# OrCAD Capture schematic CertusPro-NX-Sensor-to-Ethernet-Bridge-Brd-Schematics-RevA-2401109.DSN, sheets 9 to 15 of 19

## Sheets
9 CrossLink_Bank 0,1,3: size B
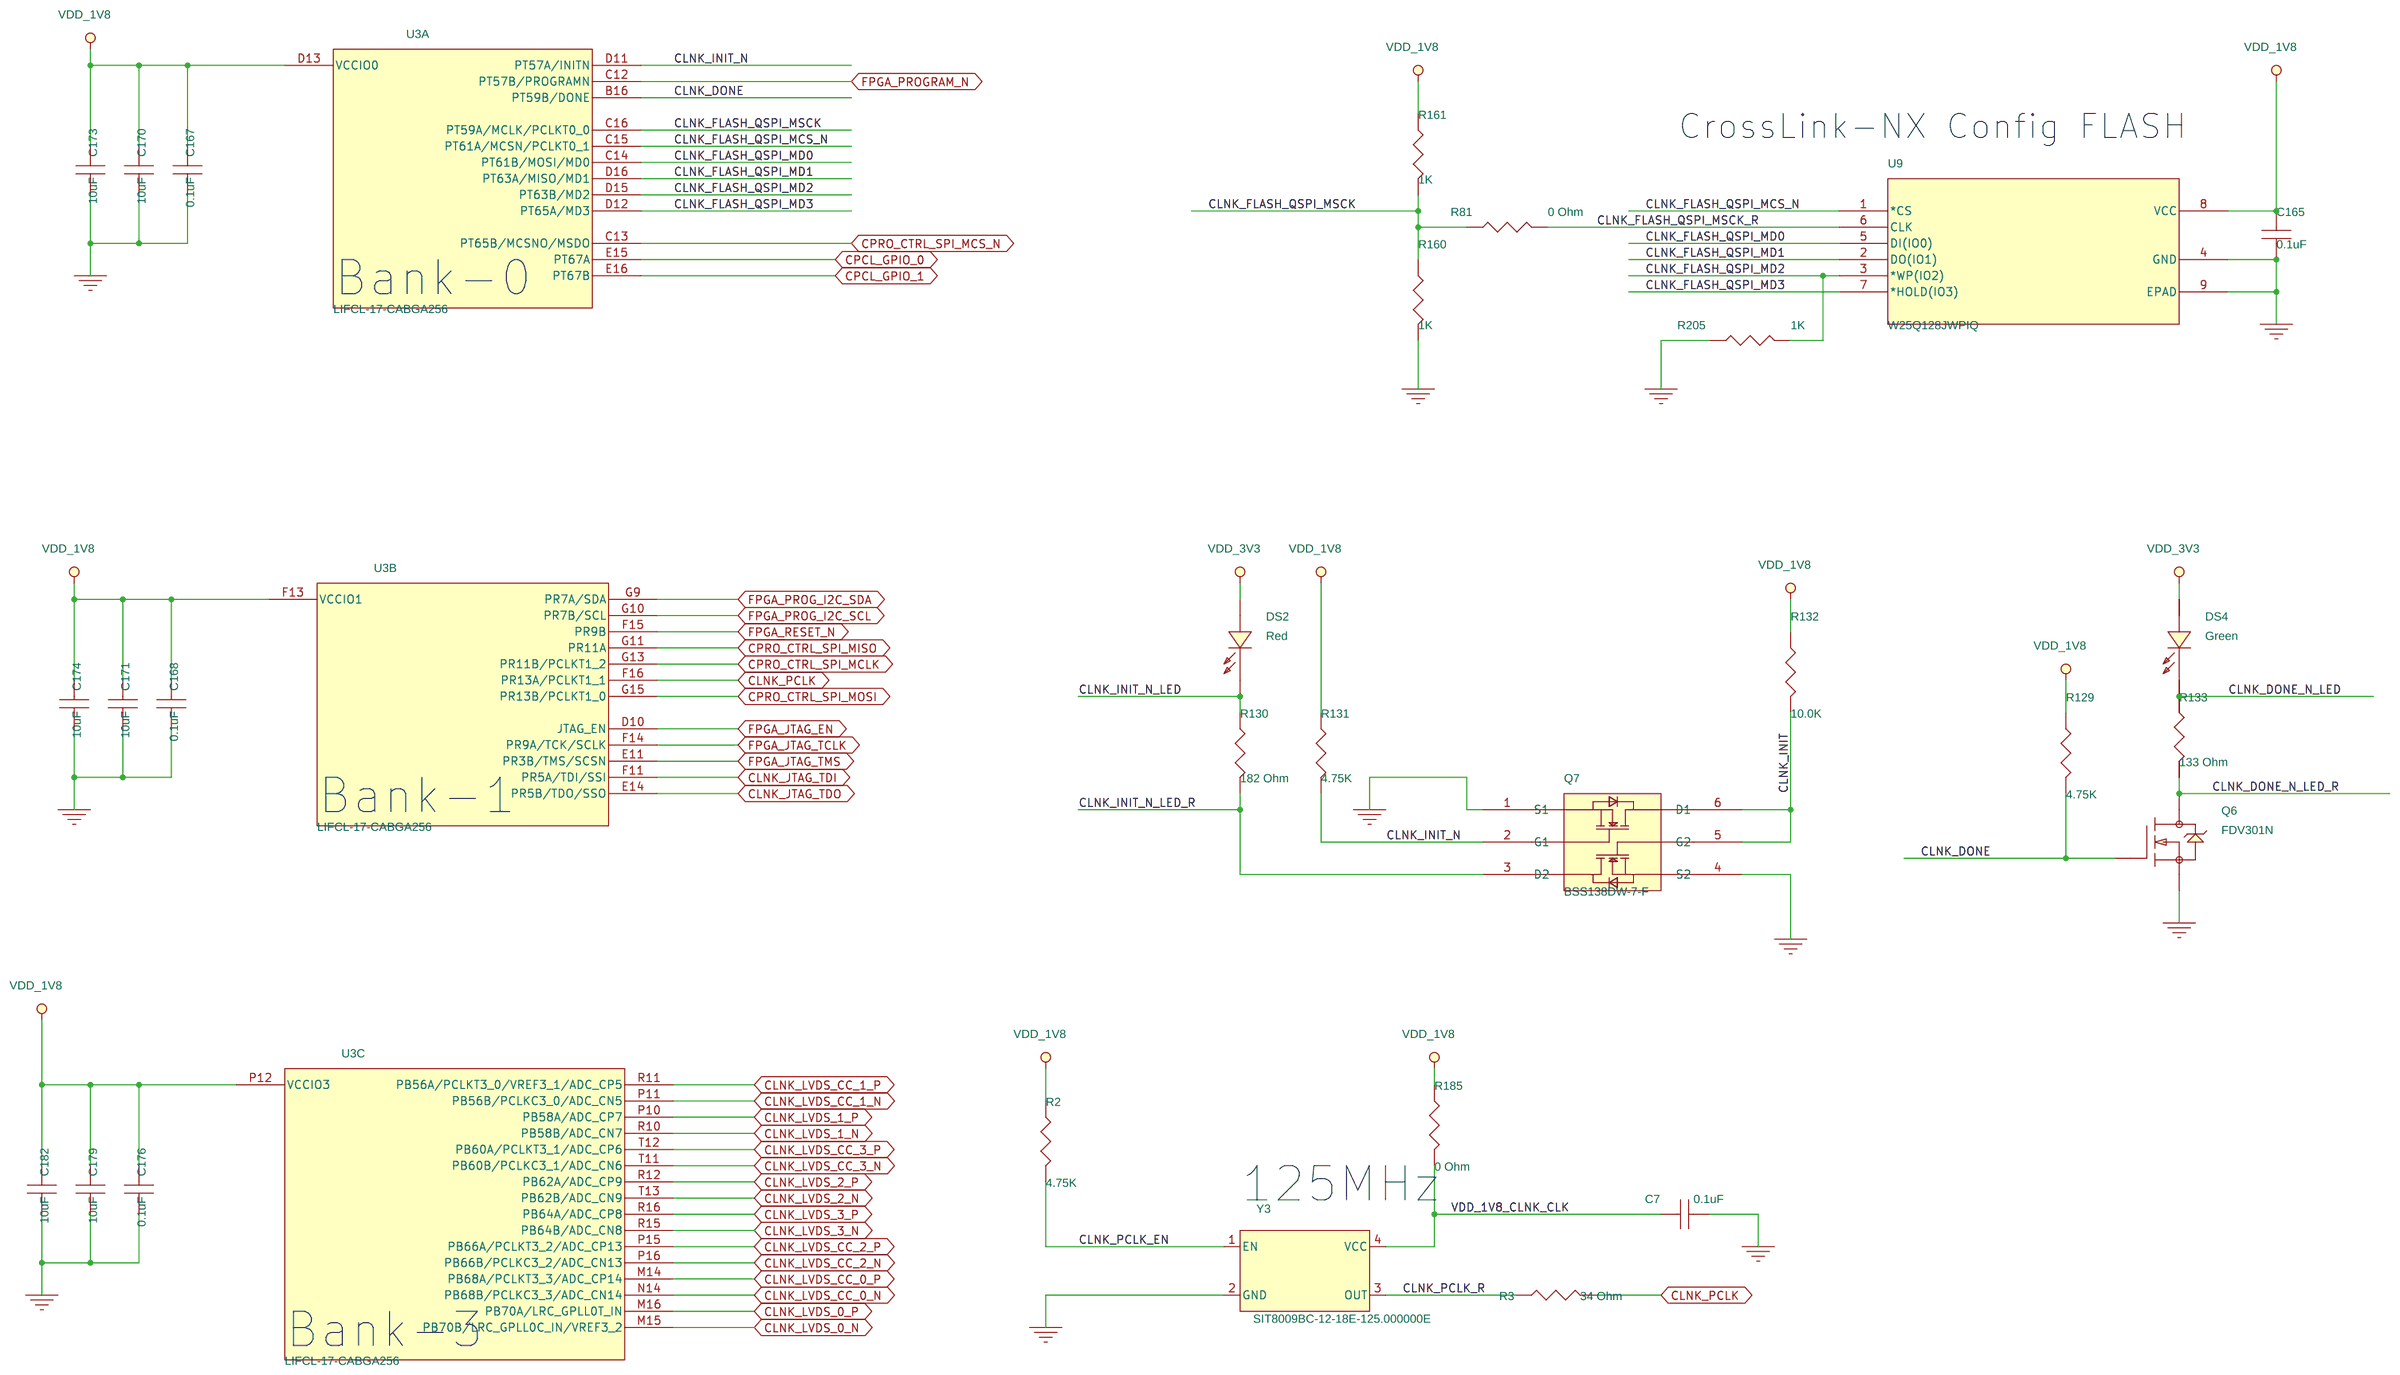
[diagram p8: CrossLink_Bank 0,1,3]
10 CrossLink_Bank 4,5,6,7: size B
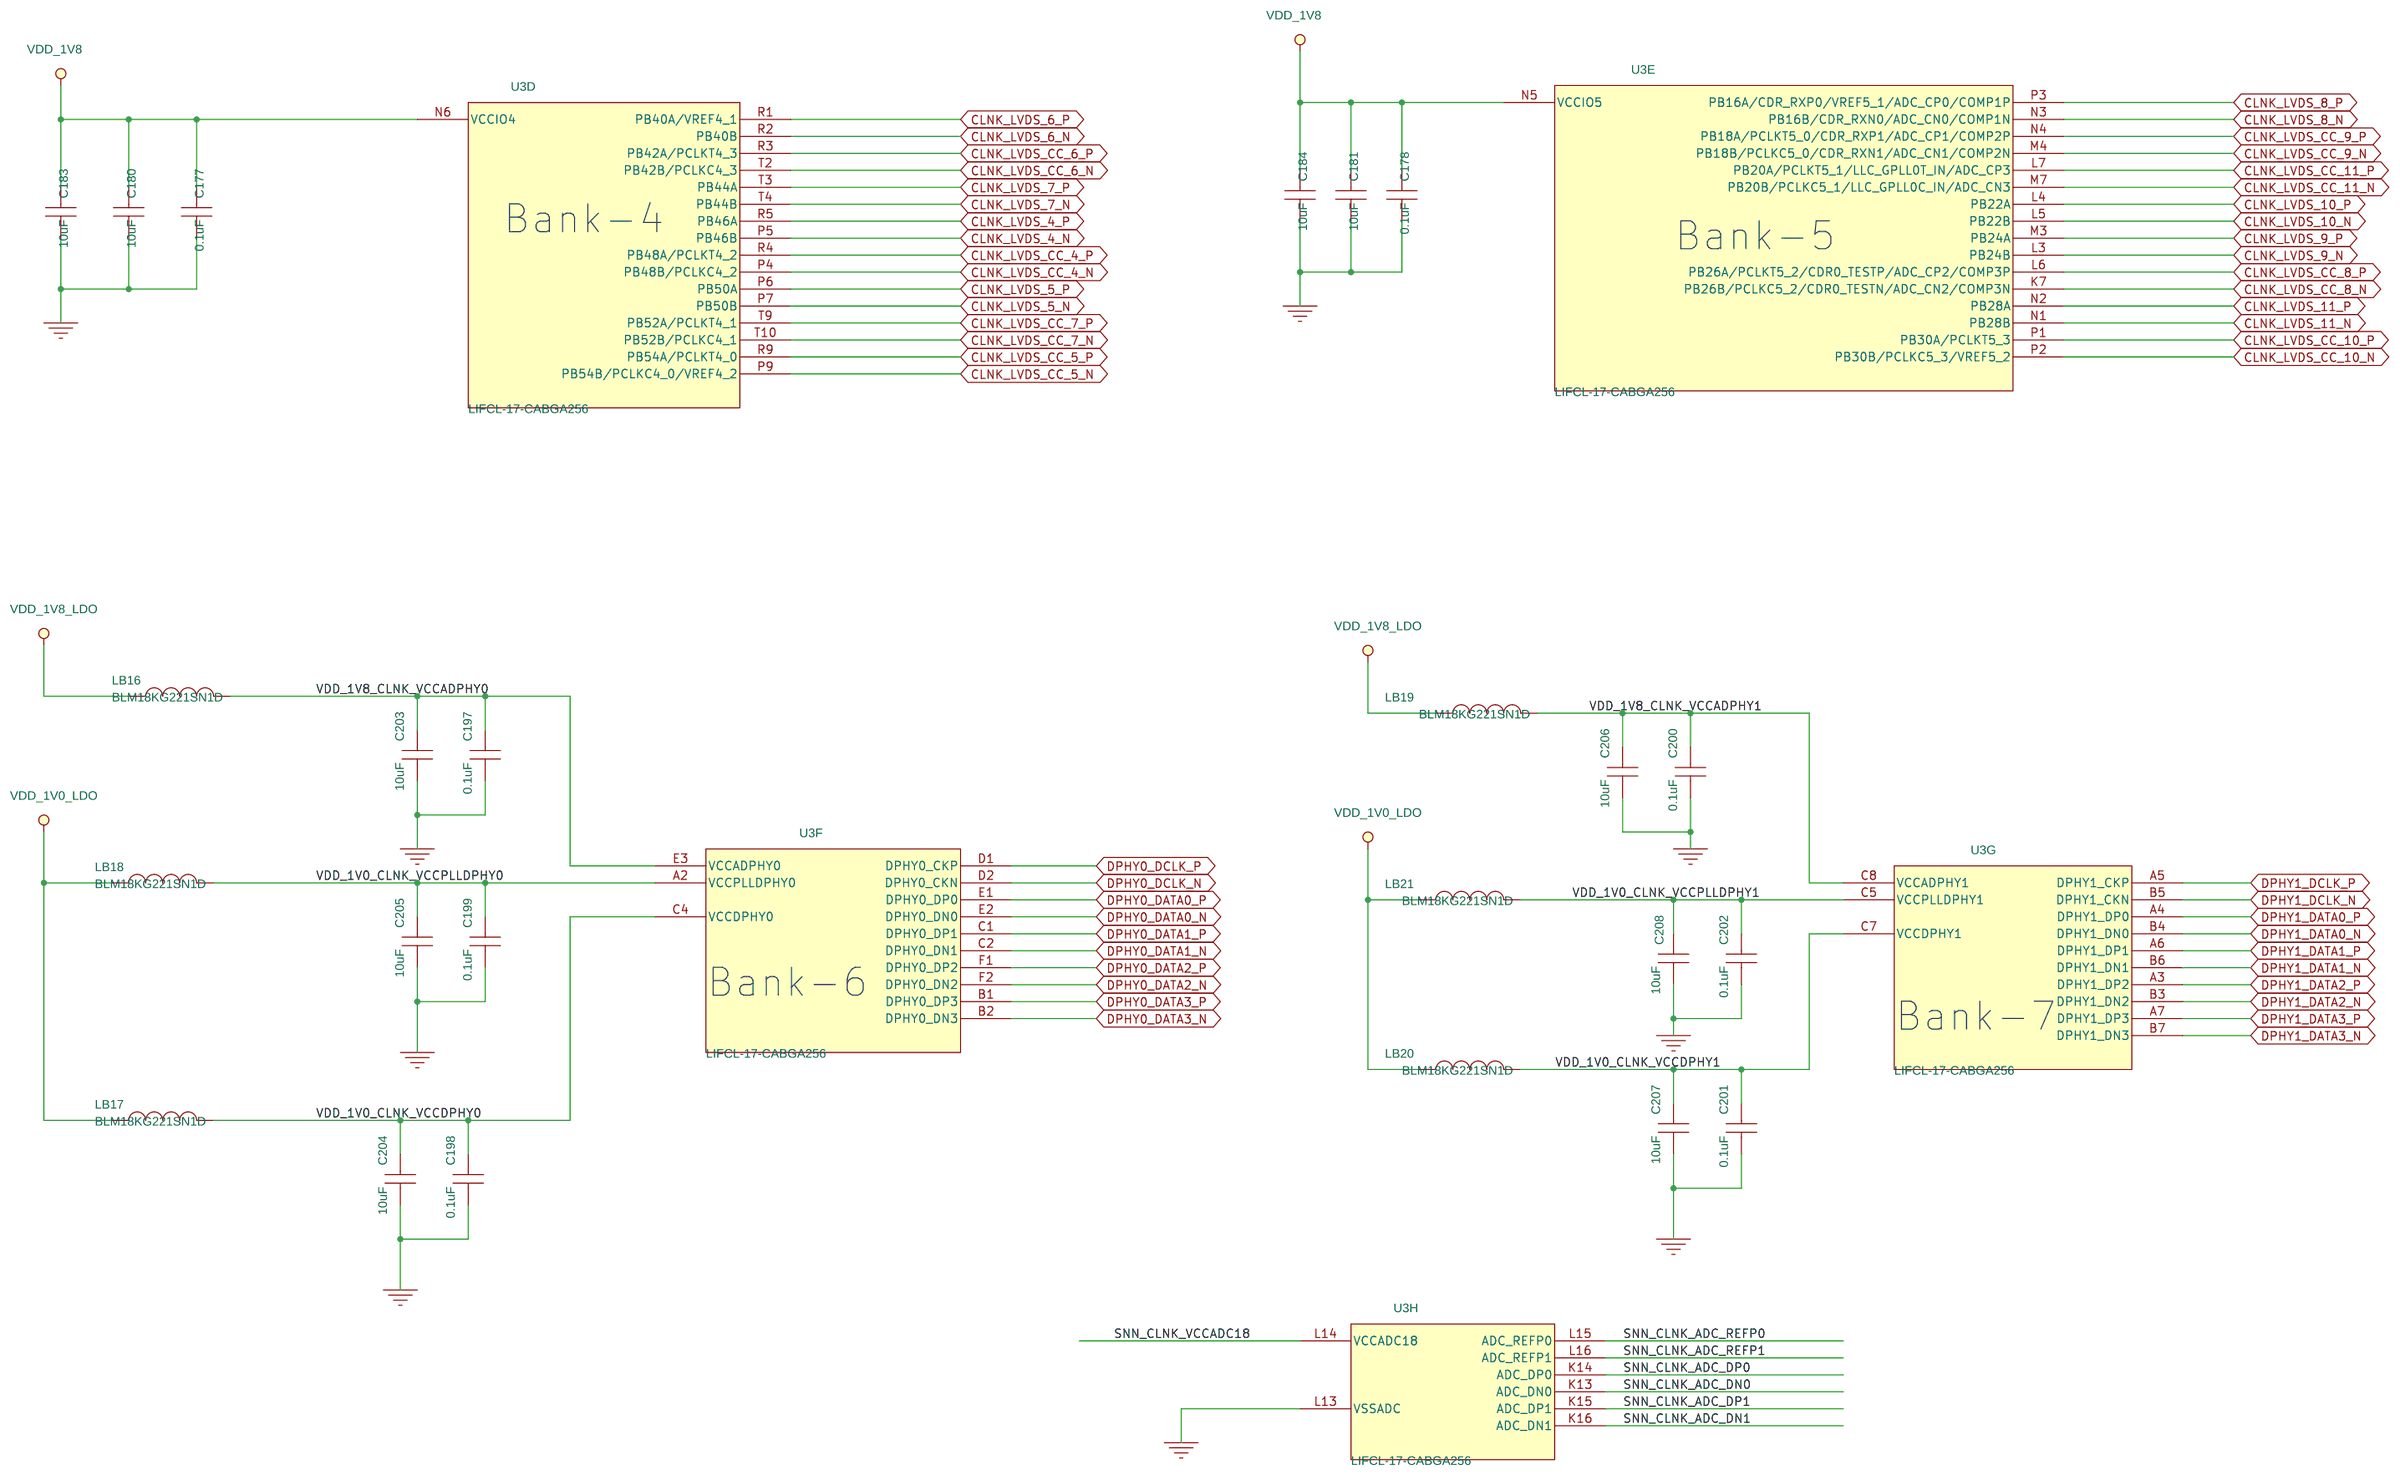
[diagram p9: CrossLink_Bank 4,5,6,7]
11 CrossLink_Power, GND: size B
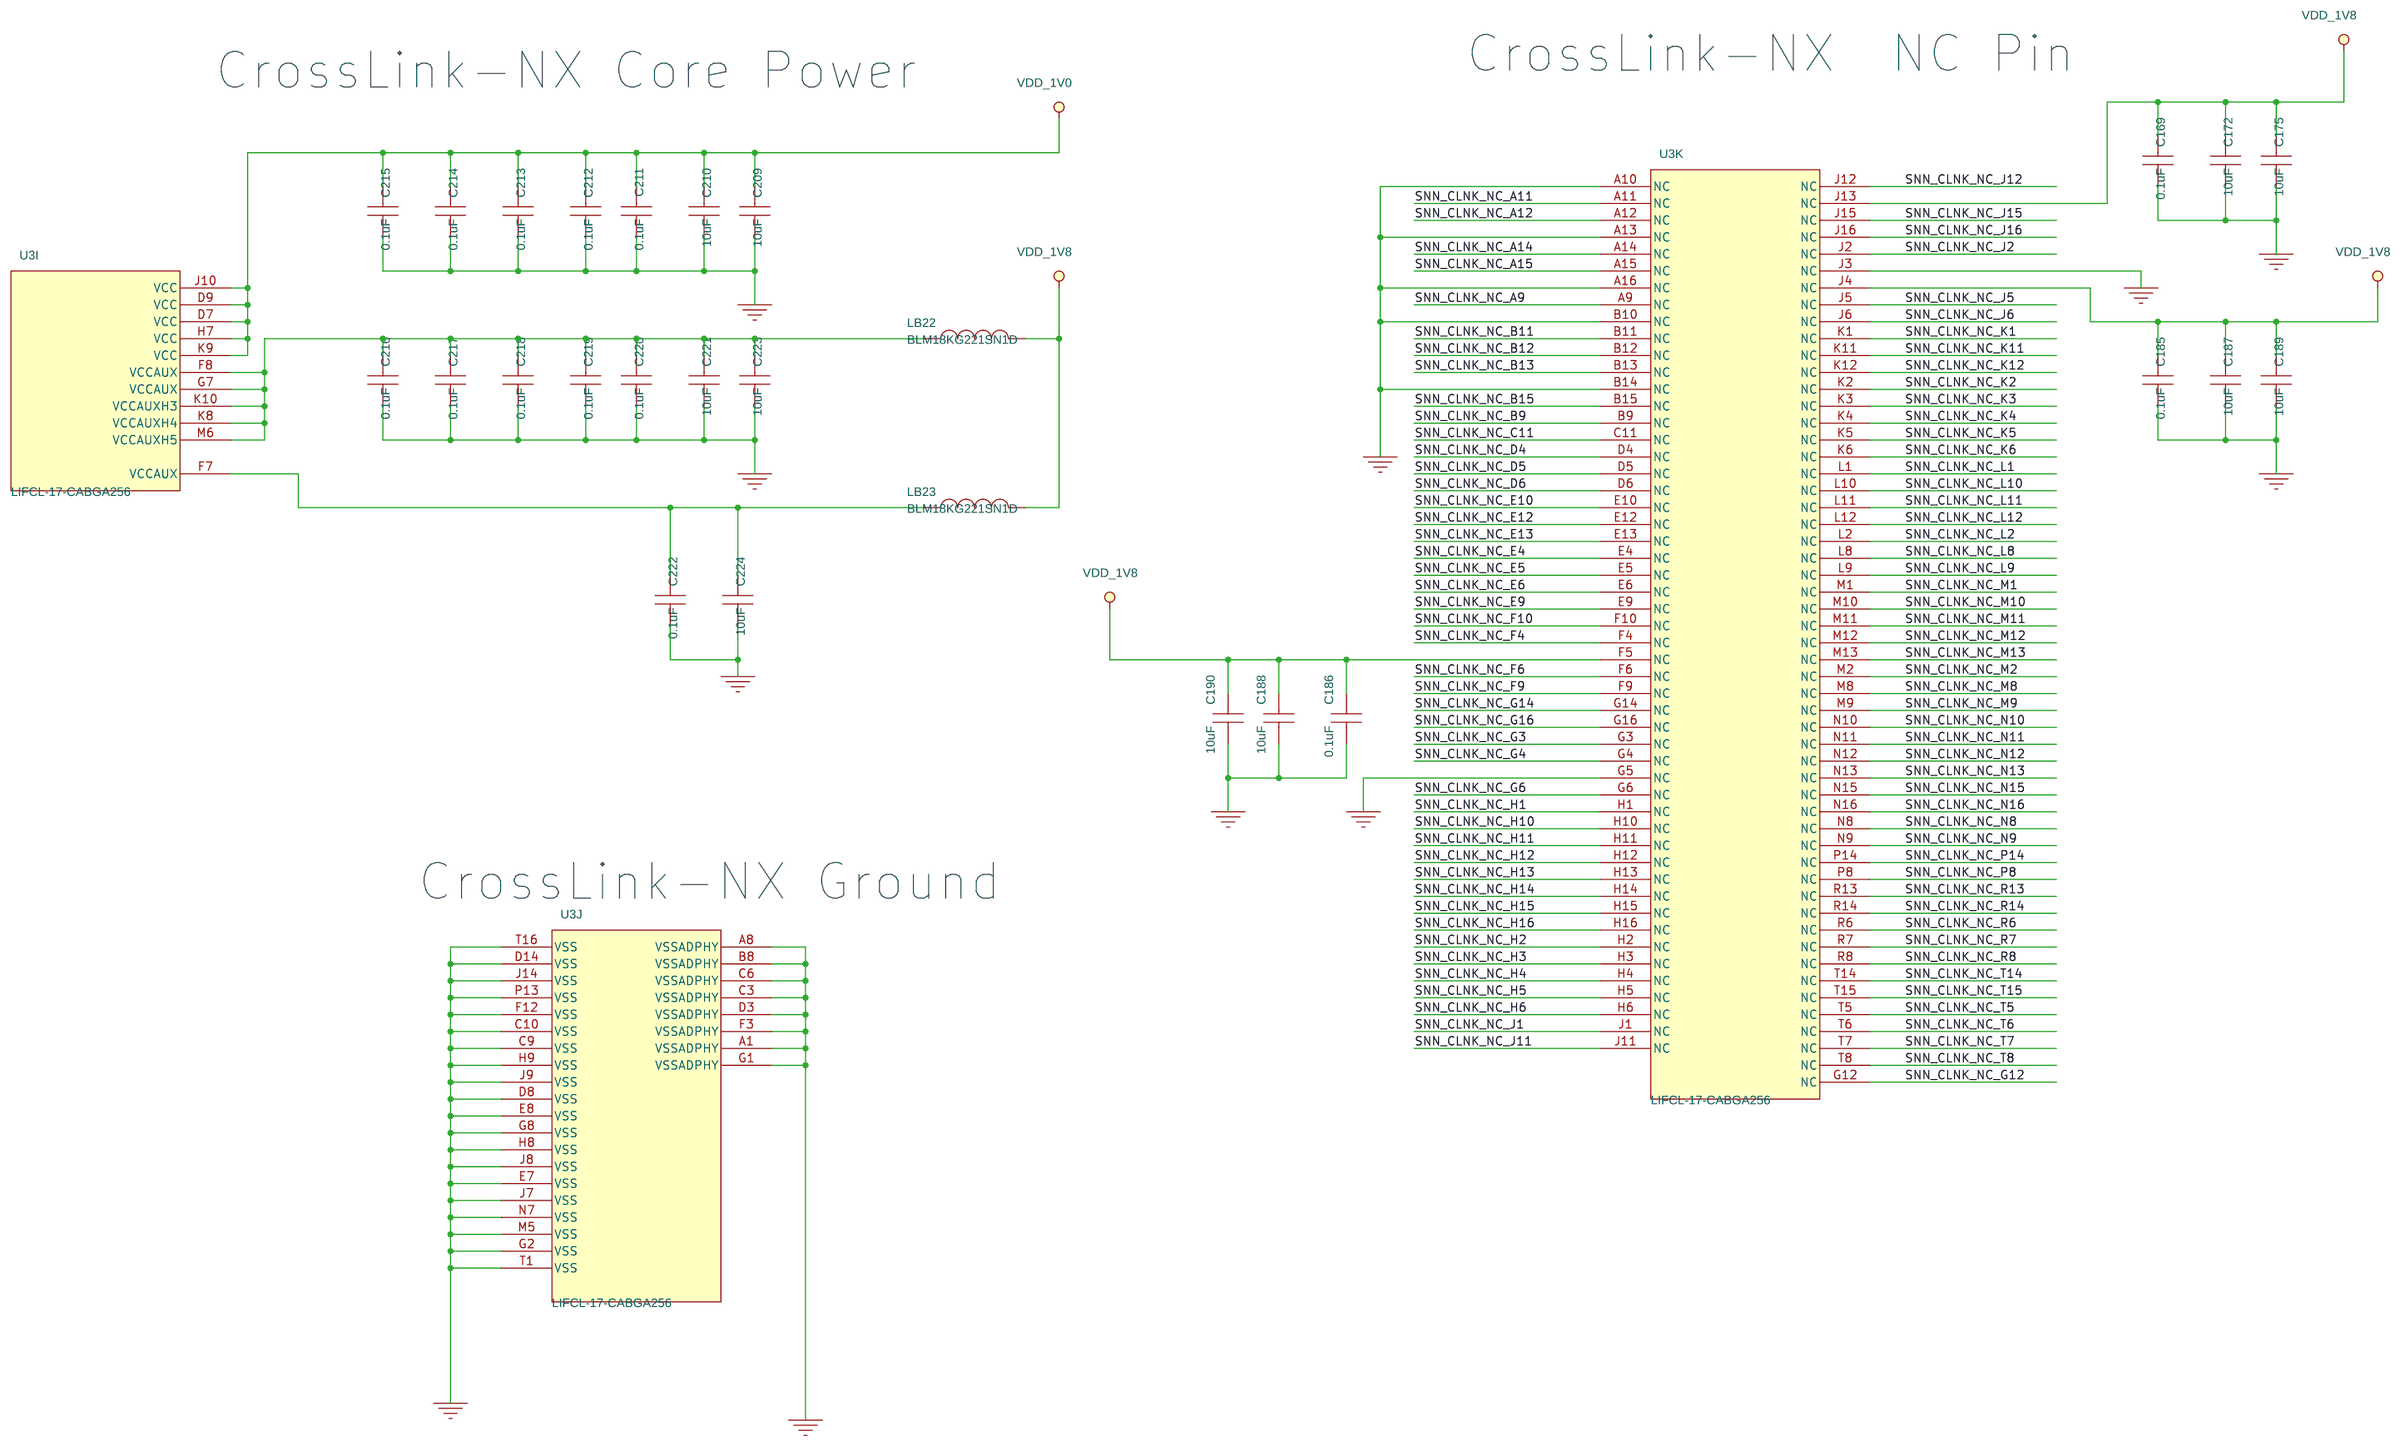
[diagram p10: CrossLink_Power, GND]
12 Camera Connector Interface: size B
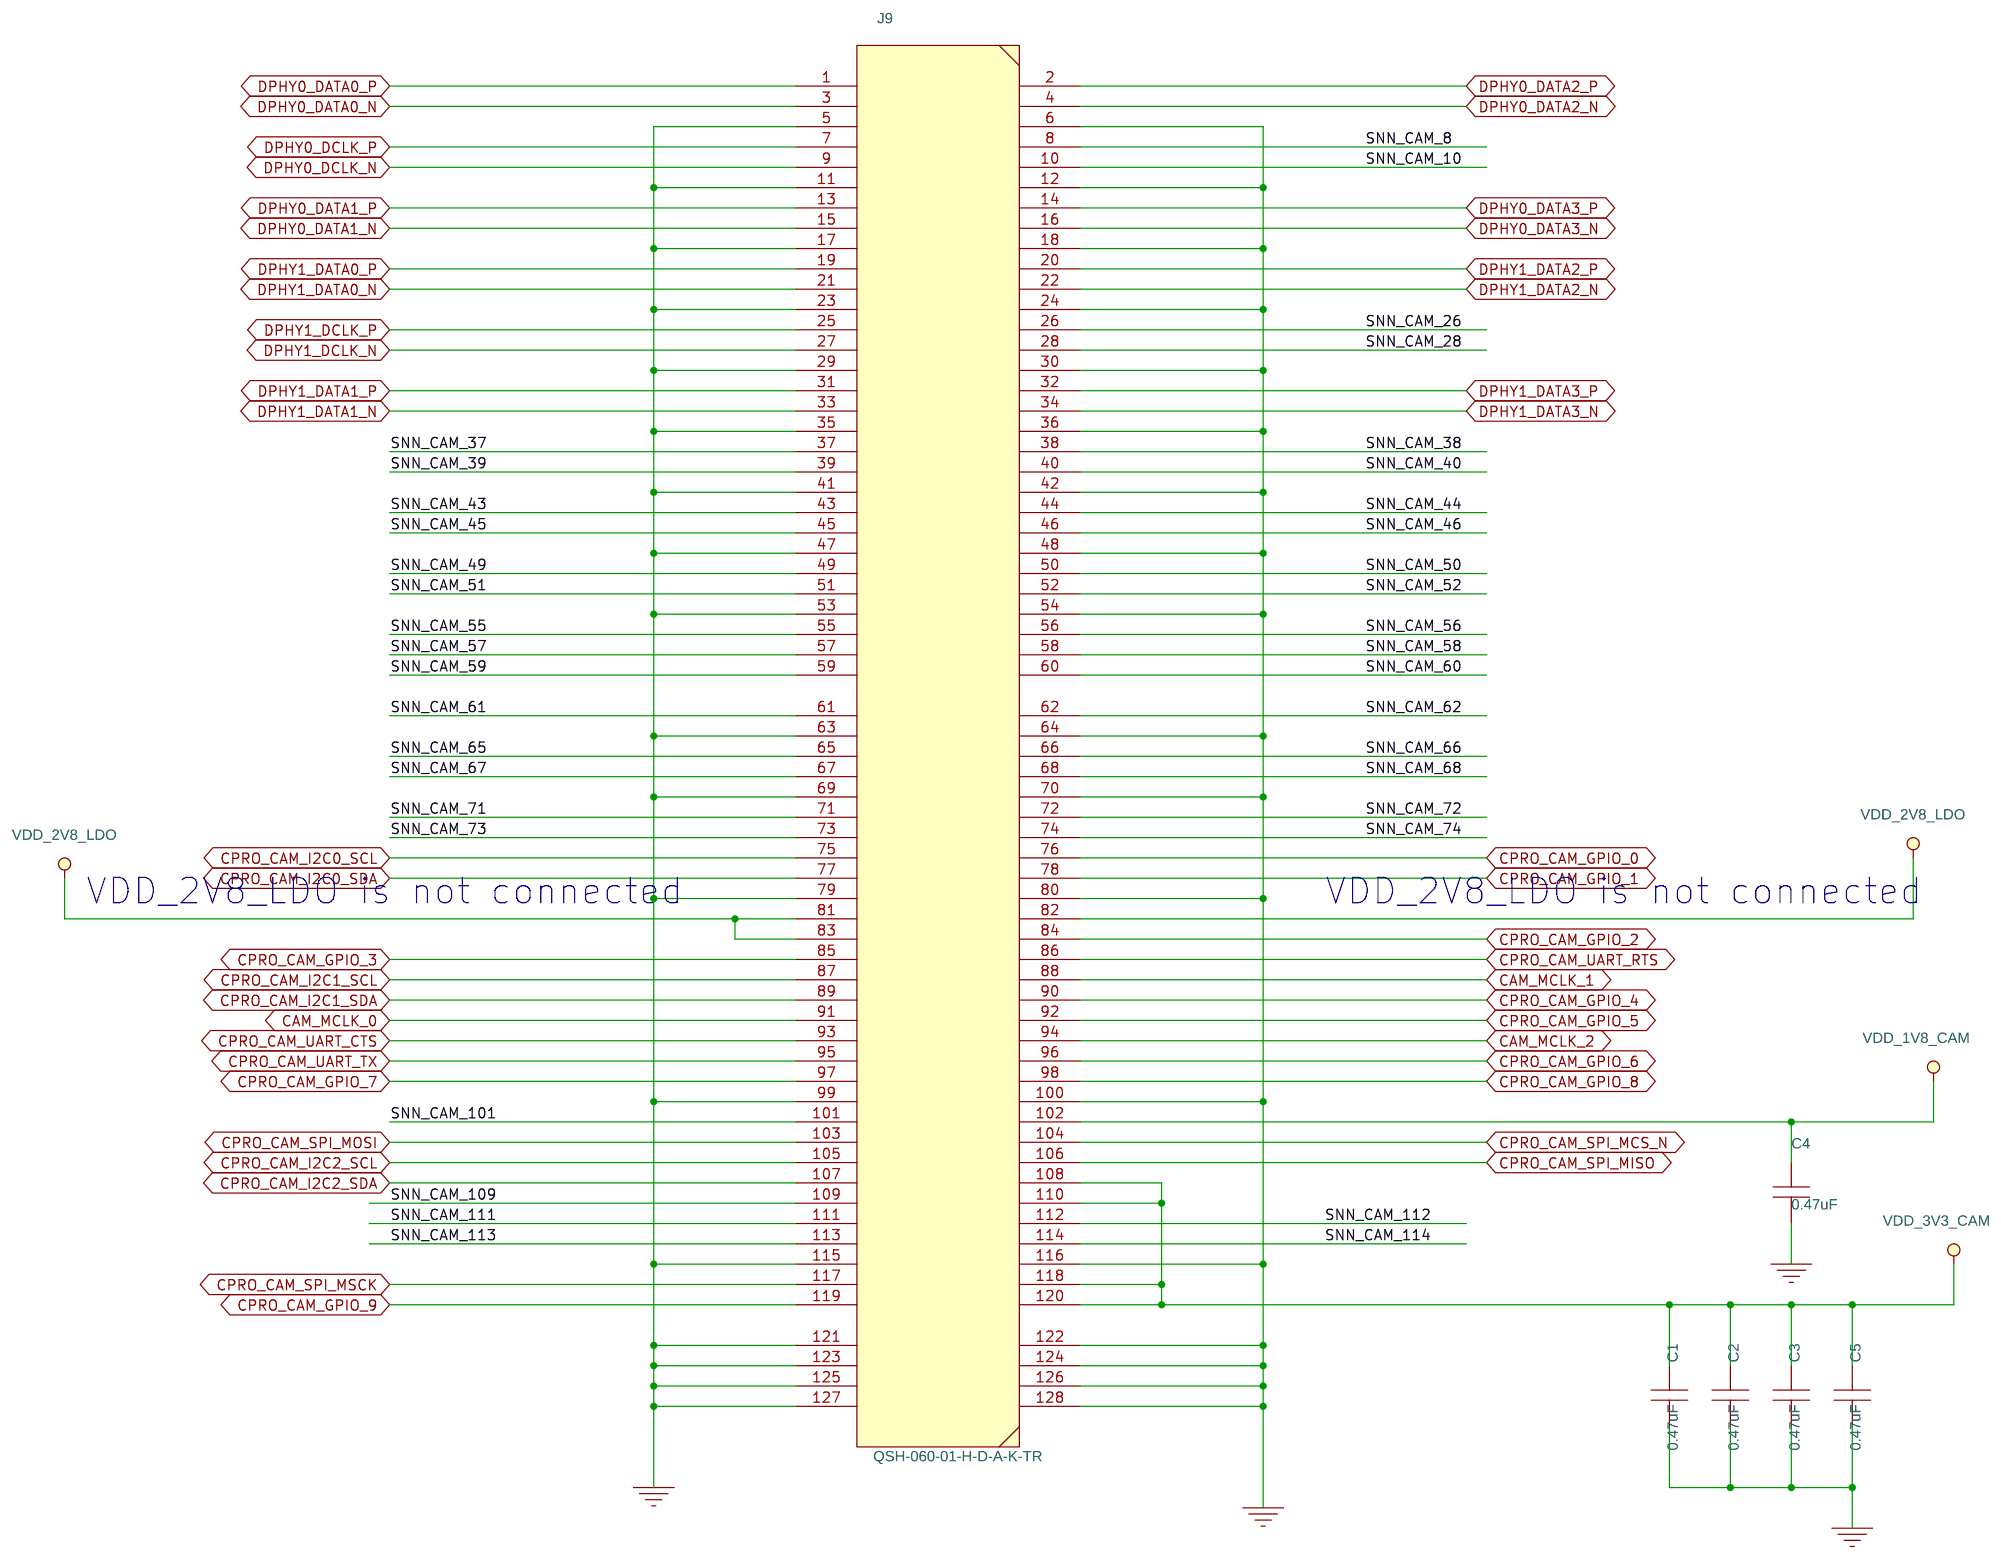
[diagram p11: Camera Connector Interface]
13 FMC HPC: size B
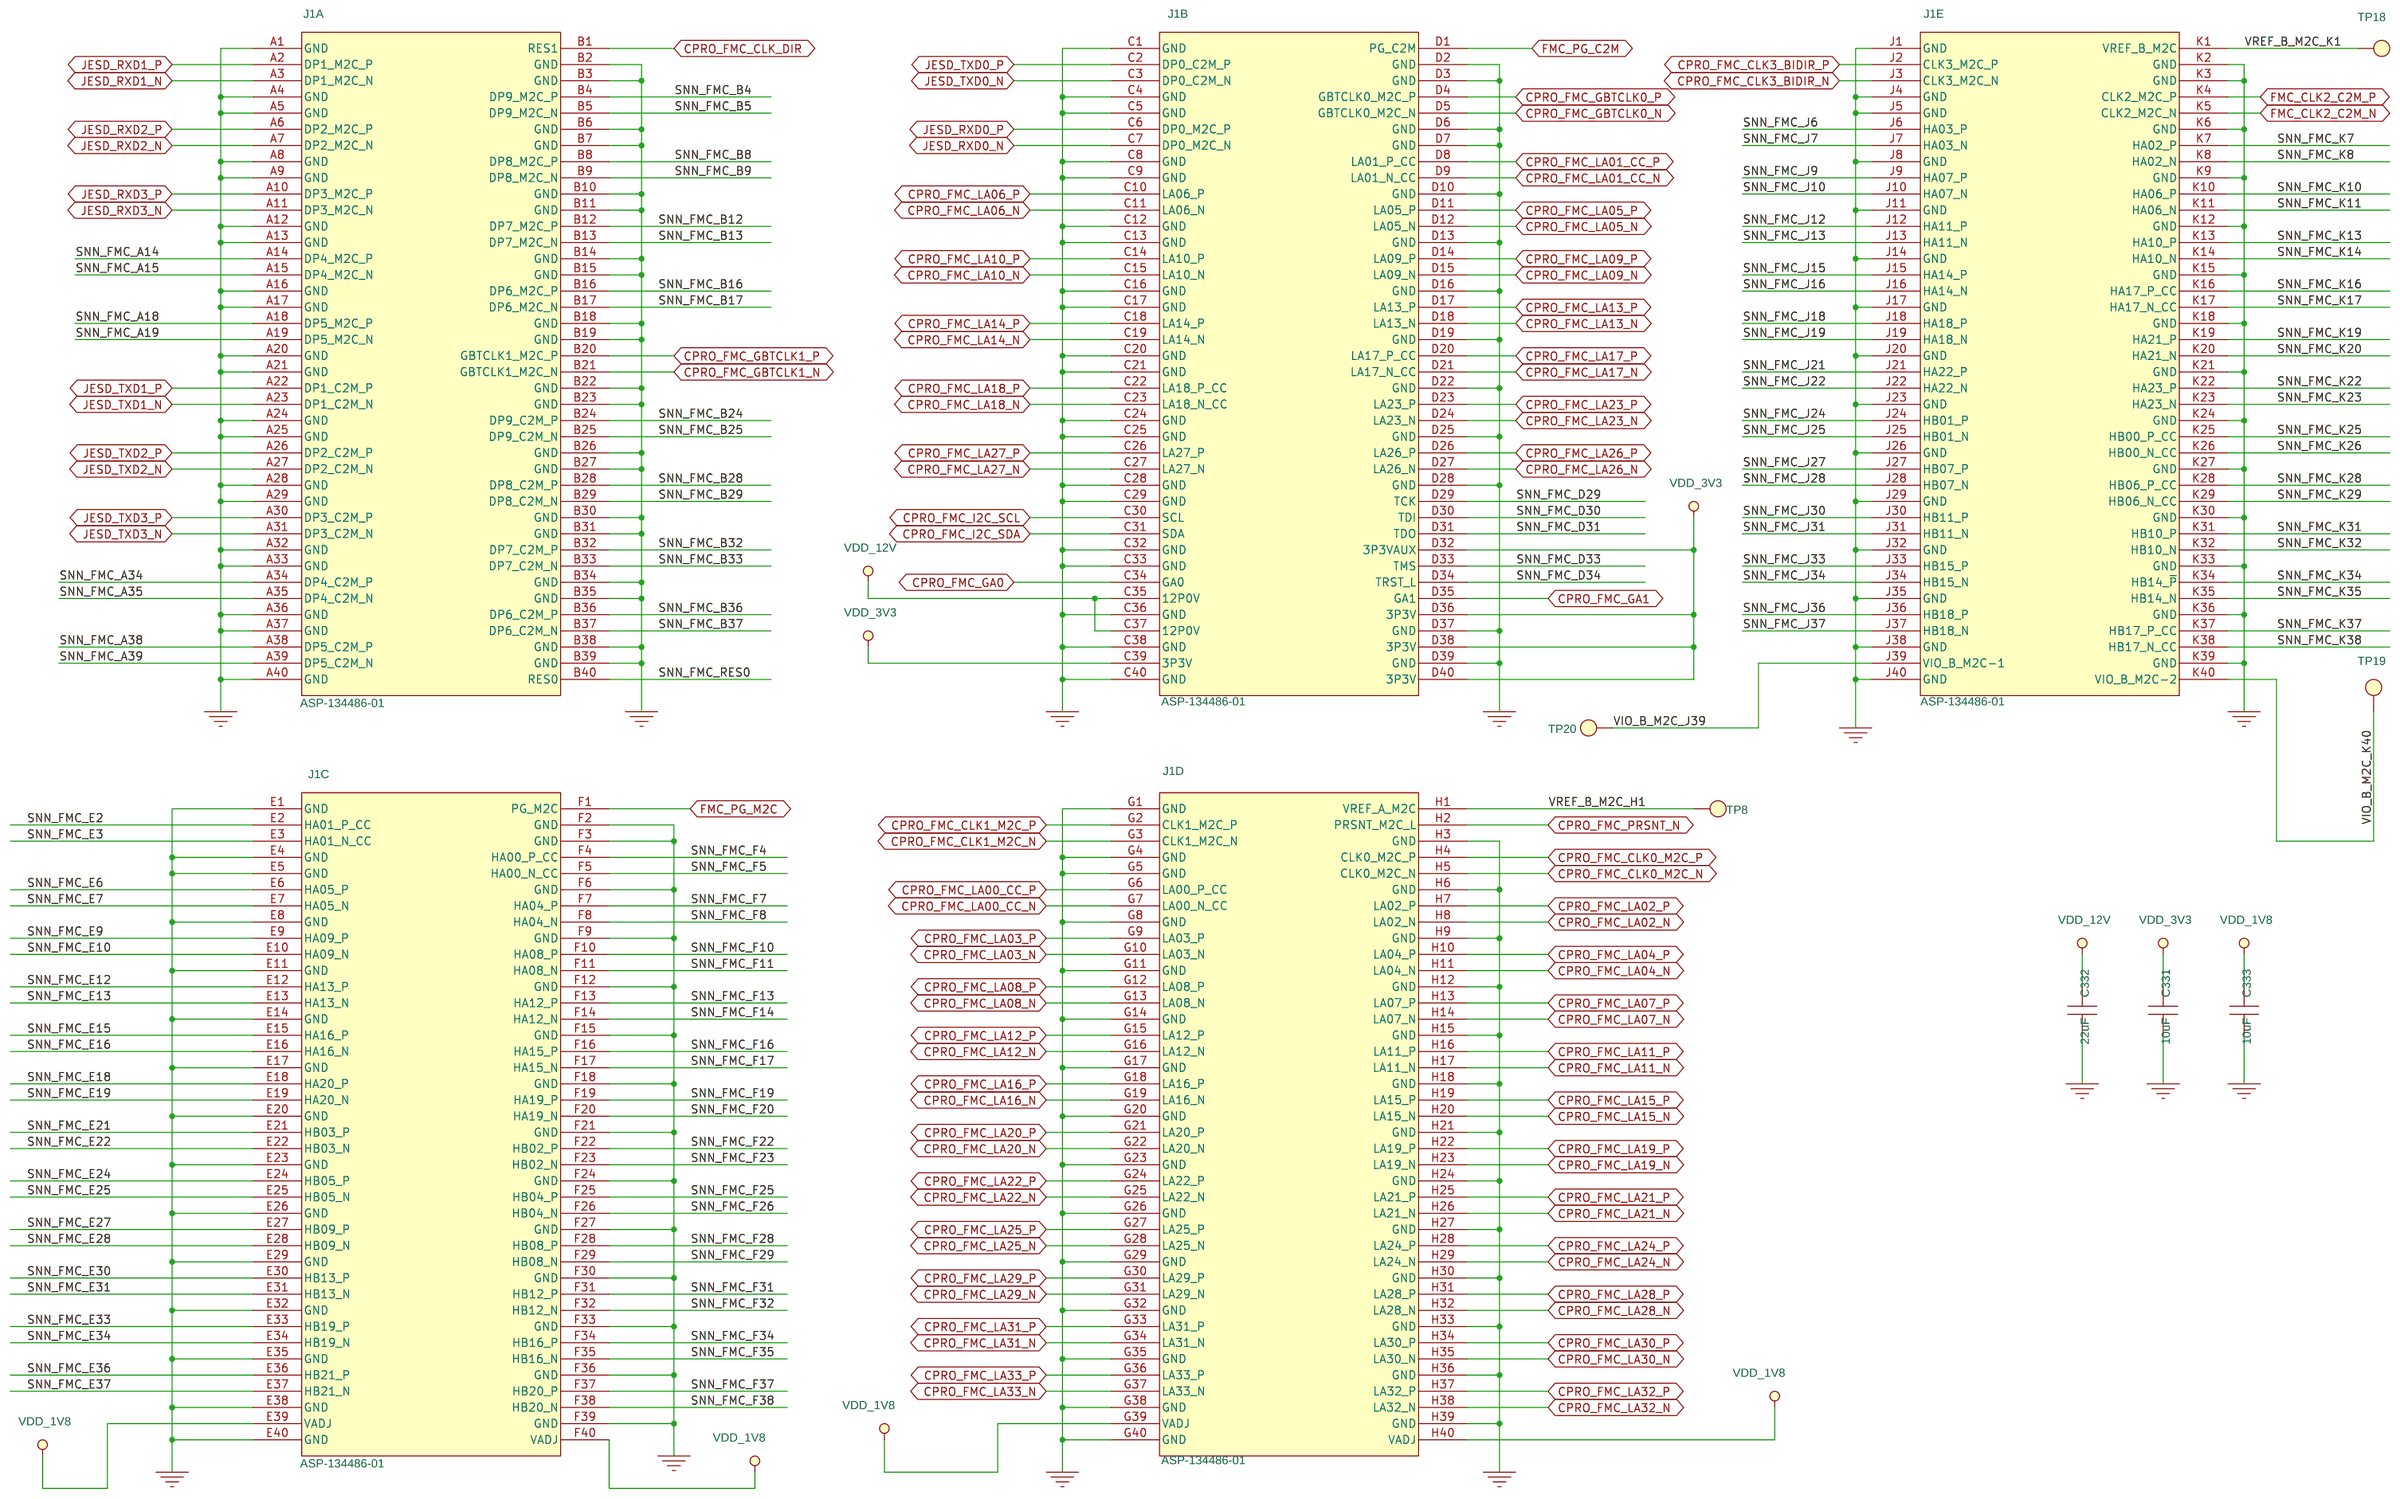
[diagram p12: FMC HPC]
14 FMC Level Shifters and Coax: size B
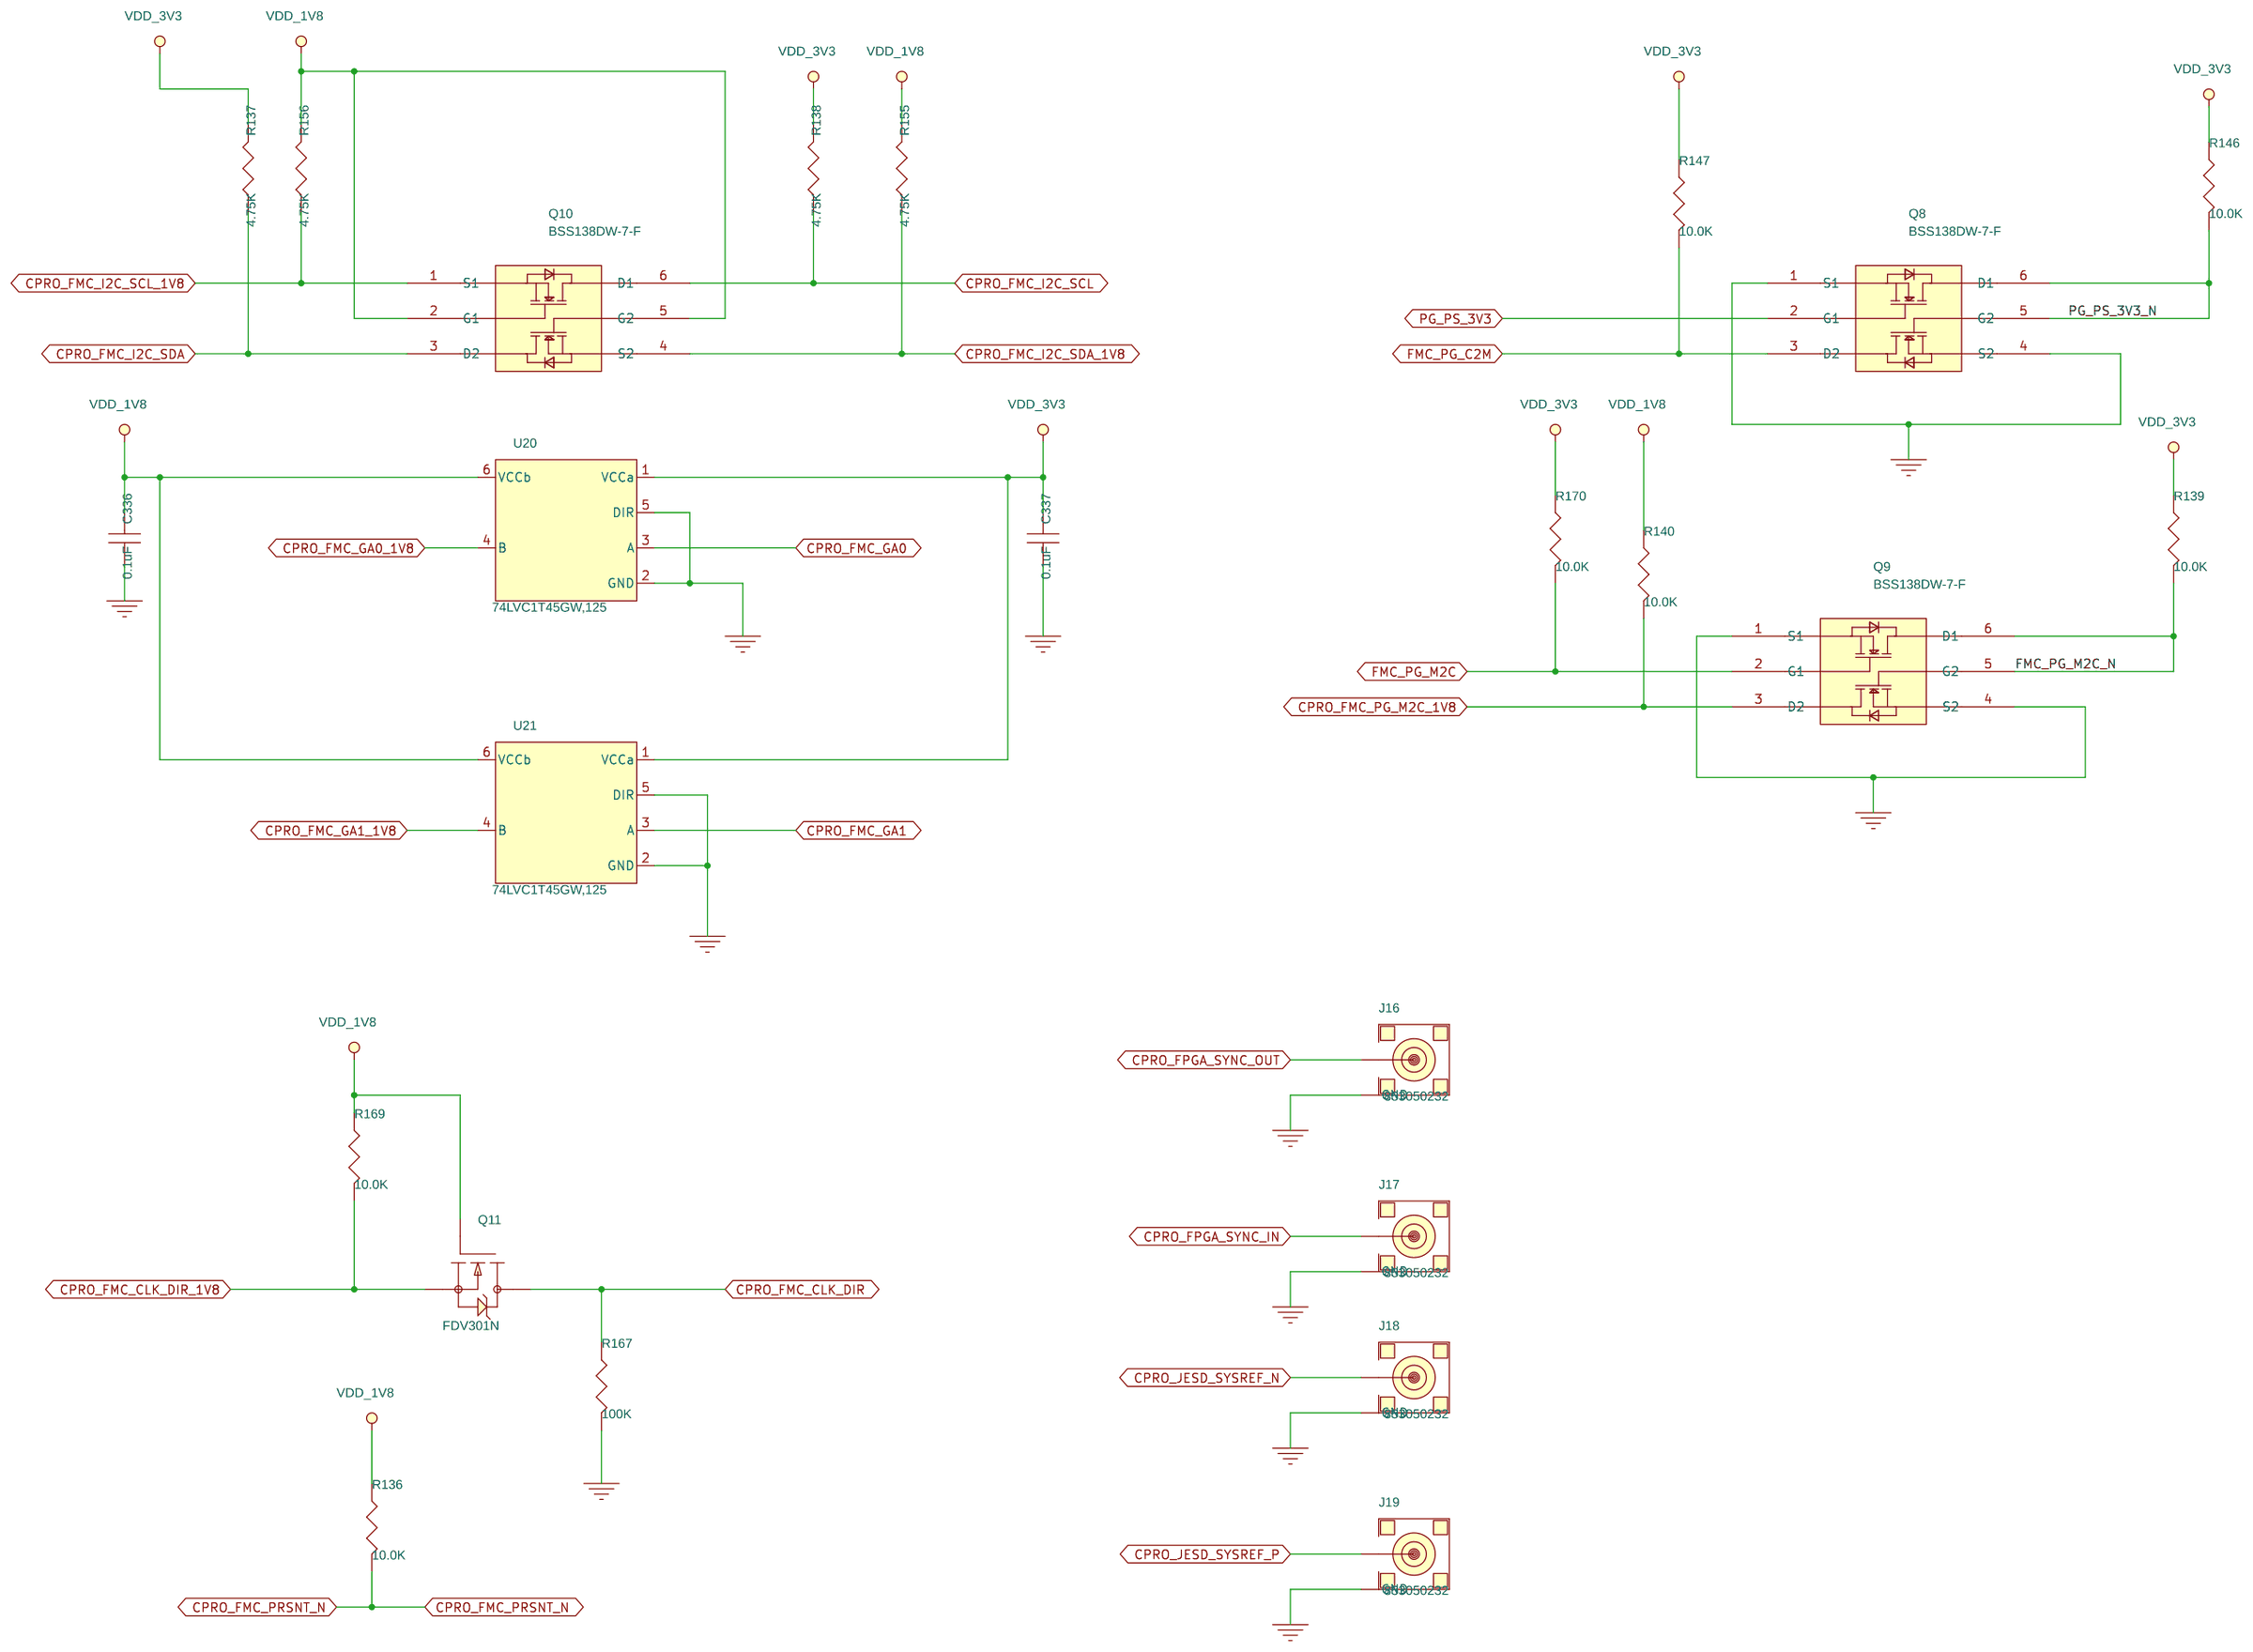
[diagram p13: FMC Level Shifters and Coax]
15 SFP+ Interface: size B
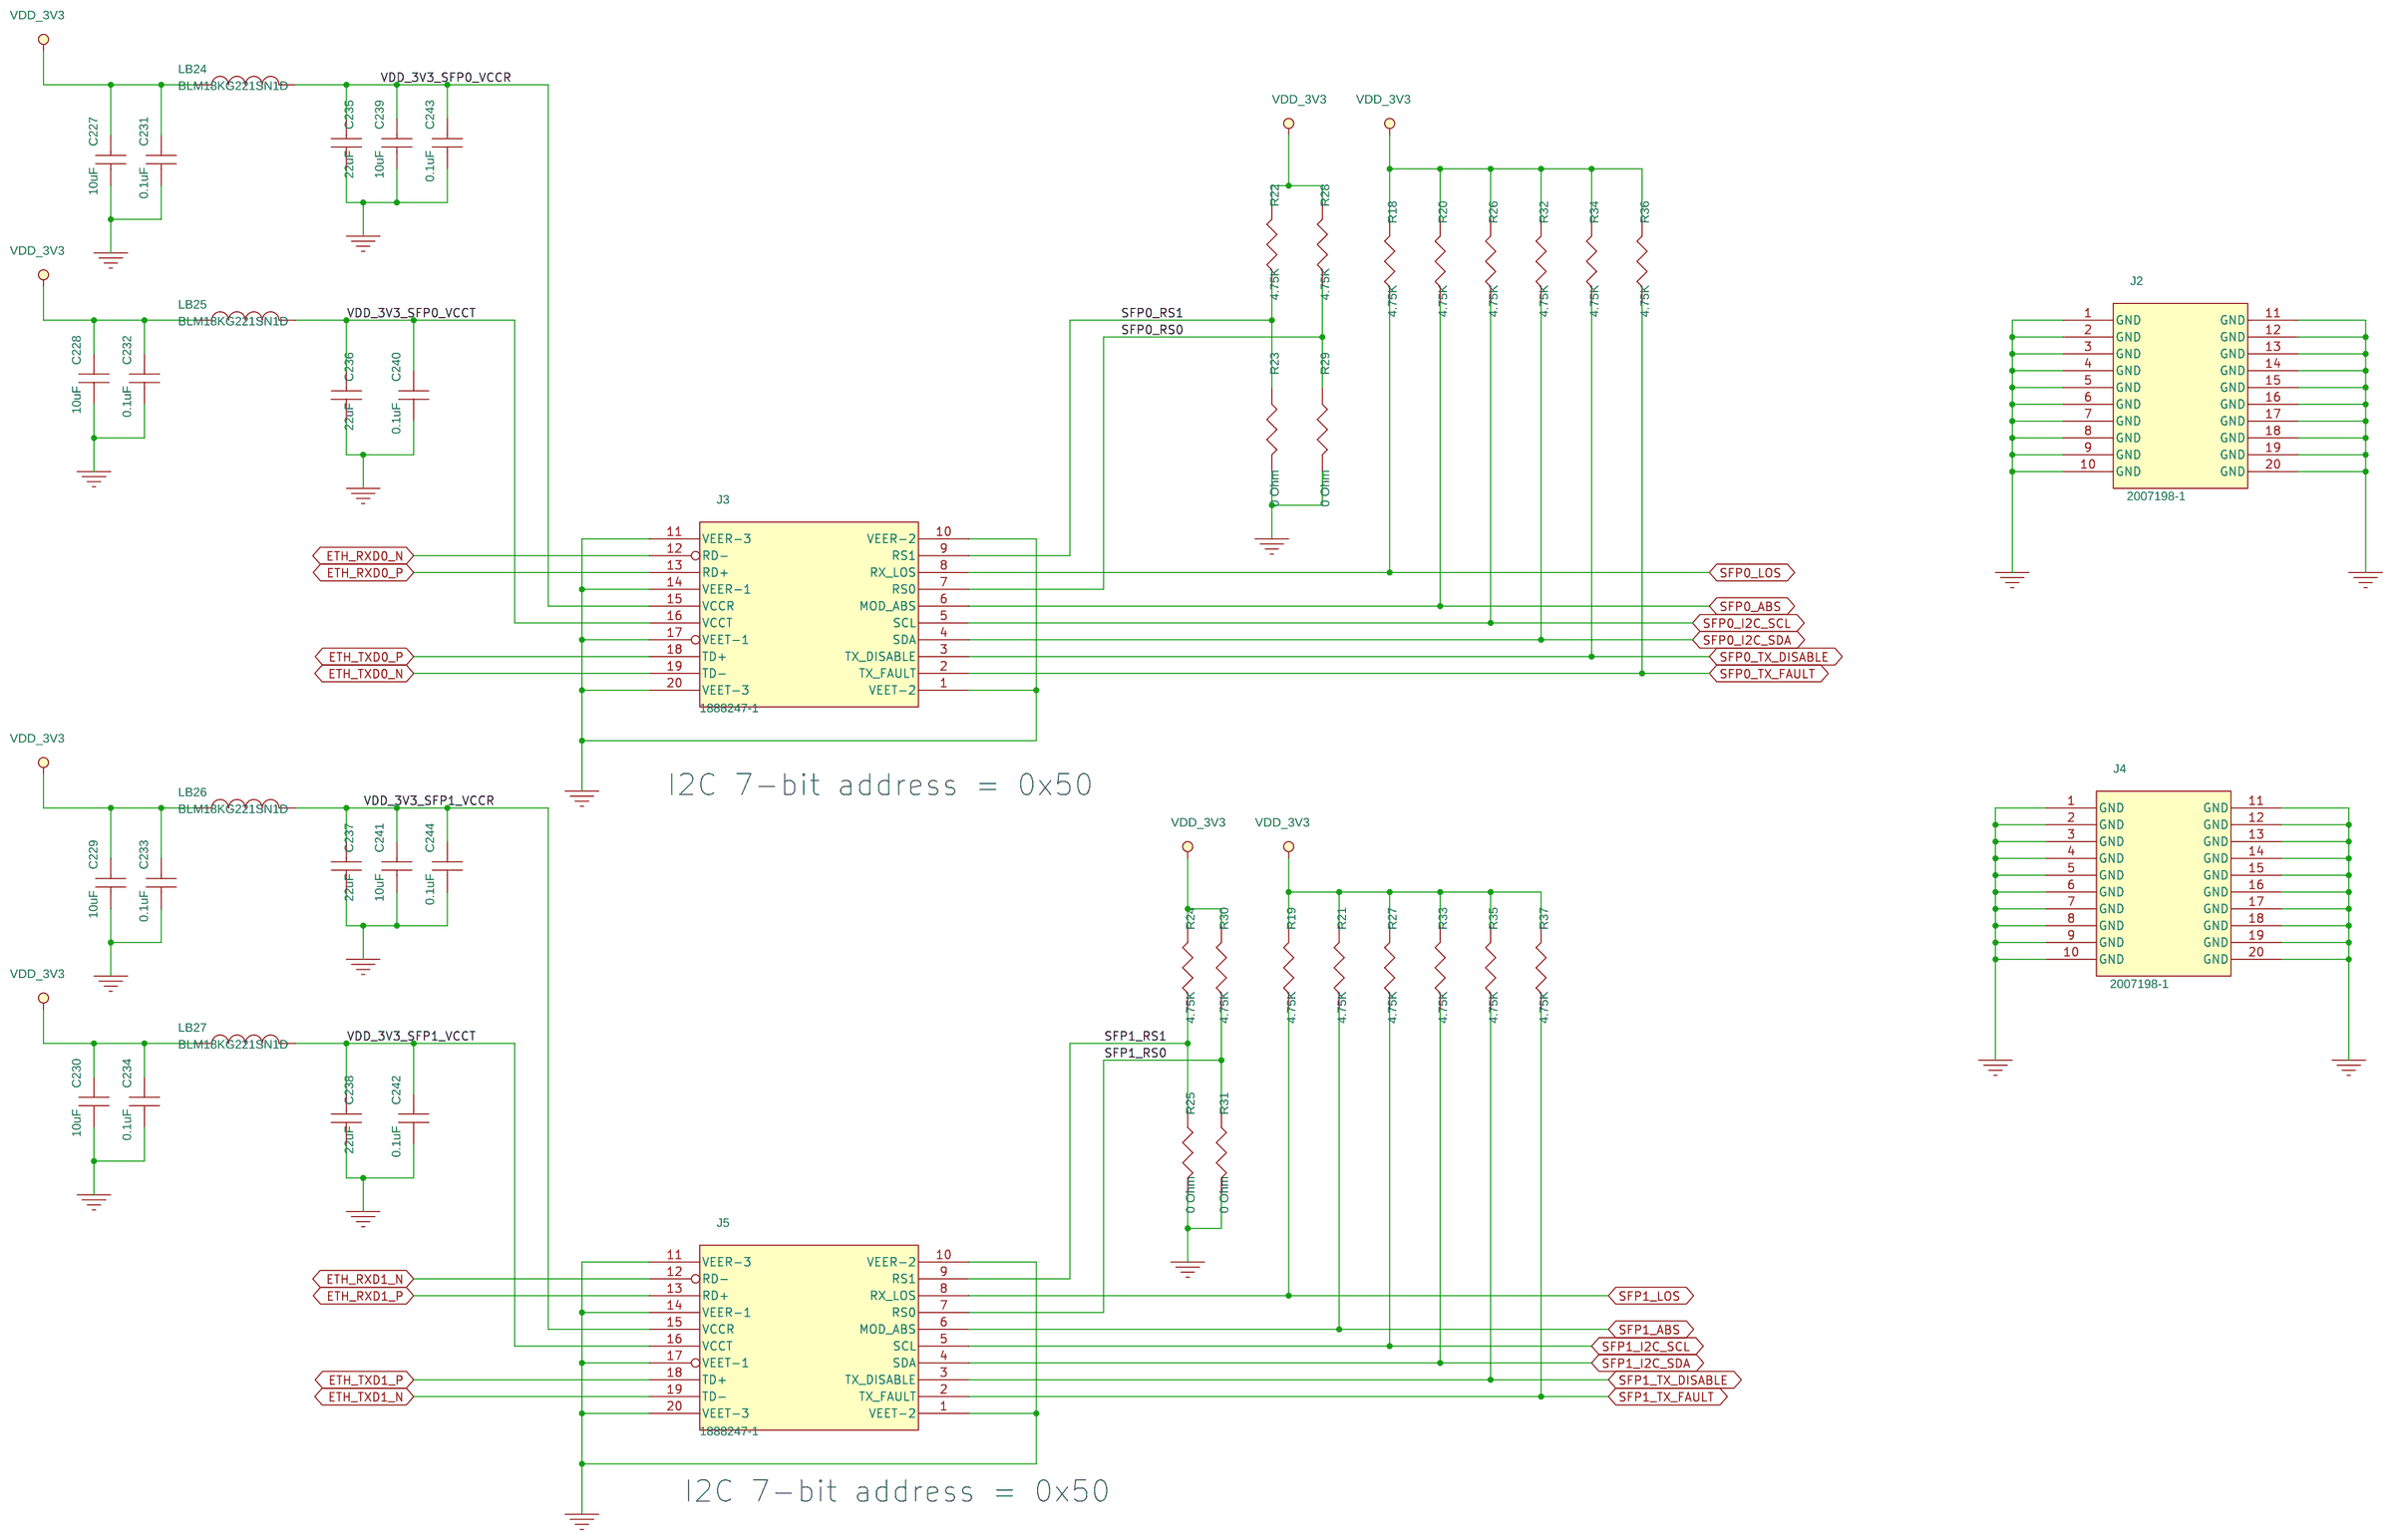
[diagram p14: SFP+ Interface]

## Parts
sheet Camera Connector Interface
C1  0.47uF  [C0402-L]
C2  0.47uF  [C0402-L]
C3  0.47uF  [C0402-L]
C4  0.47uF  [C0402-L]
C5  0.47uF  [C0402-L]
J9  QSH-060-01-H-D-A-K-TR
sheet CrossLink_Bank 0,1,3
C7  0.1uF  [C0402-L]
C165  0.1uF  [C0402-L]
C167  0.1uF  [C0402-L]
C168  0.1uF  [C0402-L]
C170  10uF  [C0603-L]
C171  10uF  [C0603-L]
C173  10uF  [C0603-L]
C174  10uF  [C0603-L]
C176  0.1uF  [C0402-L]
C179  10uF  [C0603-L]
C182  10uF  [C0603-L]
DS2  Red  [LED0603]
DS4  Green  [LED0603]
Q6  FDV301N
Q7  BSS138DW-7-F  [SOT363_DIO]
R2  4.75K  [R0402-L]
R3  34 Ohm  [R0402-L]
R81  0 Ohm  [R0402-L]
R129  4.75K  [R0402-L]
R130  182 Ohm  [R0402-L]
R131  4.75K  [R0402-L]
R132  10.0K  [R0402-L]
R133  133 Ohm  [R0402-L]
R160  1K  [R0402-L]
R161  1K  [R0402-L]
R185  0 Ohm  [R0402-L]
R205  1K  [R0402-L]
U9  W25Q128JWPIQ  [WIN_E-8_WIN]
Y3  SIT8009BC-12-18E-125.000000E
sheet CrossLink_Bank 4,5,6,7
C177  0.1uF  [C0402-L]
C178  0.1uF  [C0402-L]
C180  10uF  [C0603-L]
C181  10uF  [C0603-L]
C183  10uF  [C0603-L]
C184  10uF  [C0603-L]
C197  0.1uF  [C0402-L]
C198  0.1uF  [C0402-L]
C199  0.1uF  [C0402-L]
C200  0.1uF  [C0402-L]
C201  0.1uF  [C0402-L]
C202  0.1uF  [C0402-L]
C203  10uF  [C0603-L]
C204  10uF  [C0603-L]
C205  10uF  [C0603-L]
C206  10uF  [C0603-L]
C207  10uF  [C0603-L]
C208  10uF  [C0603-L]
LB16  BLM18KG221SN1D
LB17  BLM18KG221SN1D
LB18  BLM18KG221SN1D
LB19  BLM18KG221SN1D
LB20  BLM18KG221SN1D
LB21  BLM18KG221SN1D
sheet CrossLink_Power, GND
C169  0.1uF  [C0402-L]
C172  10uF  [C0603-L]
C175  10uF  [C0603-L]
C185  0.1uF  [C0402-L]
C186  0.1uF  [C0402-L]
C187  10uF  [C0603-L]
C188  10uF  [C0603-L]
C189  10uF  [C0603-L]
C190  10uF  [C0603-L]
C209  10uF  [C0603-L]
C210  10uF  [C0603-L]
C211  0.1uF  [C0402-L]
C212  0.1uF  [C0402-L]
C213  0.1uF  [C0402-L]
C214  0.1uF  [C0402-L]
C215  0.1uF  [C0402-L]
C216  0.1uF  [C0402-L]
C217  0.1uF  [C0402-L]
C218  0.1uF  [C0402-L]
C219  0.1uF  [C0402-L]
C220  0.1uF  [C0402-L]
C221  10uF  [C0603-L]
C222  0.1uF  [C0402-L]
C223  10uF  [C0603-L]
C224  10uF  [C0603-L]
LB22  BLM18KG221SN1D
LB23  BLM18KG221SN1D
U3  LIFCL-17-CABGA256  (sections A,B,C,D,E,F,G,H,I,J,K)
sheet FMC HPC
C331  10uF  [C0603-L]
C332  22uF  [C0805-L]
C333  10uF  [C0603-L]
J1  ASP-134486-01  [CONN_ASP-134486-01_SAI]  (sections A,B,C,D,E)
TP8  TP1  [TPd39c60]
TP18  TP1  [TPd39c60]
TP19  TP1  [TPd39c60]
TP20  TP1  [TPd39c60]
sheet FMC Level Shifters and Coax
C336  0.1uF  [C0402-L]
C337  0.1uF  [C0402-L]
J16  853050232  [SMA]
J17  853050232  [SMA]
J18  853050232  [SMA]
J19  853050232  [SMA]
Q8  BSS138DW-7-F  [SOT363_DIO]
Q9  BSS138DW-7-F  [SOT363_DIO]
Q10  BSS138DW-7-F  [SOT363_DIO]
Q11  FDV301N
R136  10.0K  [R0402-L]
R137  4.75K  [R0402-L]
R138  4.75K  [R0402-L]
R139  10.0K  [R0402-L]
R140  10.0K  [R0402-L]
R146  10.0K  [R0402-L]
R147  10.0K  [R0402-L]
R155  4.75K  [R0402-L]
R156  4.75K  [R0402-L]
R167  100K  [R0402-L]
R169  10.0K  [R0402-L]
R170  10.0K  [R0402-L]
U20  74LVC1T45GW,125  [TSSOP6_SOT363-2_NEX]
U21  74LVC1T45GW,125  [TSSOP6_SOT363-2_NEX]
sheet SFP+ Interface
C227  10uF  [C0603-L]
C228  10uF  [C0805]
C229  10uF  [C0603-L]
C230  10uF  [C0603-L]
C231  0.1uF  [C0402-L]
C232  0.1uF  [C0402-L]
C233  0.1uF  [C0402-L]
C234  0.1uF  [C0402-L]
C235  22uF  [C0805-L]
C236  22uF  [C0805]
C237  22uF  [C0805-L]
C238  22uF  [C0805-L]
C239  10uF  [C0603-L]
C240  0.1uF  [C0402-L]
C241  10uF  [C0603-L]
C242  0.1uF  [C0402-L]
C243  0.1uF  [C0402-L]
C244  0.1uF  [C0402-L]
J2  2007198-1
J3  1888247-1
J4  2007198-1
J5  1888247-1
LB24  BLM18KG221SN1D
LB25  BLM18KG221SN1D
LB26  BLM18KG221SN1D
LB27  BLM18KG221SN1D
R18  4.75K  [R0402-L]
R19  4.75K  [R0402-L]
R20  4.75K  [R0402-L]
R21  4.75K  [R0402-L]
R22  4.75K  [R0402-L]
R23  0 Ohm  [R0402-L]
R24  4.75K  [R0402-L]
R25  0 Ohm  [R0402-L]
R26  4.75K  [R0402-L]
R27  4.75K  [R0402-L]
R28  4.75K  [R0402-L]
R29  0 Ohm  [R0402-L]
R30  4.75K  [R0402-L]
R31  0 Ohm  [R0402-L]
R32  4.75K  [R0402-L]
R33  4.75K  [R0402-L]
R34  4.75K  [R0402-L]
R35  4.75K  [R0402-L]
R36  4.75K  [R0402-L]
R37  4.75K  [R0402-L]

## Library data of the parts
C1-C5 = CAP_NP: CAP NCS X5R 0402 0.47uF +/-10% 6.3V; Manufacturer: Murata Manufacturing Co., Ltd.; Manufacturer Part Number: GRM155R60J474KE19D; Part Number: GRM155R60J474KE19D; Part type: Ceramic; Tolerance: 10%; Voltage: 6.3V
J9 = QSH-060-01: 120 Position Connector Receptacle, Center Strip Contacts Surface Mount Gold
C7 C165 C232 = CAP_NP: 0.1 µF ±10% 50V Ceramic Capacitor X7R 0402 (1005 Metric); Manufacturer: Murata; Manufacturer Part Number: GRM155R71H104KE14J; Part Number: GRM155R71H104KE14J; Part type: Ceramic; Tolerance: 10%; Voltage: 50V; Datasheet: https://search.murata.co.jp/Ceramy/image/img/A01X/G101/ENG/GRM155R71H104KE14-01.pdf
C167-C169 C176-C178 C185 C186 C197-C202 C211-C220 C222 C231 C233 C234 C242-C244 C336 C337 = CAP_NP: CAP CER 0.1UF 16V X7R 0402; Manufacturer: KEMET; Manufacturer Part Number: C0402C104K4RACTU; Part Number: C0402C104K4RACTU; Part type: Ceramic; Tolerance: 10%; Voltage: 16V
C170-C175 C179-C184 C187-C190 C203-C210 C221 C223 C224 C227 C229 C230 C239 C241 C331 C333 = CAP_NP: CAP CER 10UF 6.3V X5R 0603; Manufacturer: KEMET; Manufacturer Part Number: C0603C106M9PAC7867; Part Number: C0603C106M9PAC7867; Part type: Ceramic; Tolerance: 20%; Voltage: 6.3V
DS2 = LED: LED 0603 SML-D12U1W 2.2V 20mA Red 620nm 63mcd; Current: 20mA; Manufacturer: ROHM Co., Ltd.; Manufacturer Part Number: SML-D12U1W; Part Number: SML-D12U1W; Voltage: 2.2V
DS4 = LED: LED 0603 KPT-1608-RY231 2.5V 30mA Green 5V VER; Current: 30mA; Manufacturer: Kingbright Electronic Co., Ltd.; Manufacturer Part Number: KPT-1608-RY231; Part Number: KPT-1608-RY231; Voltage: 2.5V
Q6 Q11 = N-MOS: MOSFET N-CH 25V 220MA SOT23; Manufacturer: ON Semiconductor Corporation; Part Type: MOSFET N-CH; Datasheet: https://www.onsemi.com/pdf/datasheet/fdv301n-d.pdf
Q7-Q10 = BSS138DW-7: MOSFET 2N-CH 50V 0.2A SOT363; Manufacturer: Diodes Incorporated; Part Type: MOSFET N-CH; Datasheet: https://www.diodes.com/assets/Datasheets/ds30203.pdf
R2 R18-R22 R24 R26-R28 R30 R32-R37 R129 R131 R137 R138 R155 R156 = R: RES 0402 4.75kohm 1% 62.5mW; Manufacturer: Matsushita Electric Works, Ltd.; Manufacturer Part Number: ERJ2RKF4751X; Part Number: ERJ2RKF4751X; Part type: Thick Film; Power: 62.5mW; Tolerance: 1%
R3 = R: RES 0402 34ohm 1% 62.5mW; Manufacturer: Yageo Corporation; Manufacturer Part Number: RC0402FR-0734RL; Part Number: RC0402FR-0734RL; Part type: Thick Film; Power: 50rporationFR-; Tolerance: 1%
R23 R25 R29 R31 R81 R185 = R: 0 Ohms Jumper Chip Resistor 0402 (1005 Metric) Moisture Resistant Thick Film; Manufacturer: Yageo; Manufacturer Part Number: RC0402FR-070RL; Part Number: RC0402FR-070RL; Part type: Thick Film; Datasheet: https://www.yageo.com/upload/media/product/productsearch/datasheet/rchip/PYu-RC_Group_51_RoHS_L_12.pdf
R130 = R: RES 0402 182ohm 1% 62.5mW; Manufacturer: Matsushita Electric Works, Ltd.; Manufacturer Part Number: ERJ2RKF1820X; Part Number: ERJ2RKF1820X; Part type: Thick Film; Power: 62.5mW; Tolerance: 1%
R132 R136 R139 R140 R146 R147 R169 R170 = R: 10 kOhms ±1% 0.063W, 1/16W Chip Resistor 0402 (1005 Metric) Thick Film; Manufacturer: Yageo; Manufacturer Part Number: RC0402FR-0710KP; Part Number: RC0402FR-0710KP; Part type: Thick Film; Power: 1/16W; Tolerance: 1%; Datasheet: https://www.yageo.com/upload/media/product/products/datasheet/rchip/PYu-RC_51_RoHS_P_4.pdf
R133 = R: RES 0402 133ohm 1% 62.5mW; Manufacturer: SAMSUNG ELECTRONICS CO., LTD.; Manufacturer Part Number: RC1005F1330CS; Part Number: RC1005F1330CS; Part type: Thick Film; Power: 62.5mW; Tolerance: 1%
R160 R161 R205 = R: RES 0402 1kohm 1% 62.5mW; Manufacturer: TA-I Technology Co., Ltd.; Manufacturer Part Number: RM04FTN1001; Part Number: RM04FTN1001; Part type: Thick Film; Power: 62.5mW; Tolerance: 1%
U9 = W25Q128JW: FLASH - NOR Memory IC 128Mbit SPI - Quad I/O 133 MHz 8-WSON (6x5); Manufacturer: Winbond Electronics Corporation; Part Type: FLASH; Datasheet: https://www.winbond.com/resource-files/W25Q128JW_RevG_07292021%20Plus.pdf
Y3 = SiT8009B_1: MEMS OSC XO 125.0000MHZ H/LVCMOS; Manufacturer: SiTime Corporation; Part Type: Oscillator; Datasheet: https://www.sitime.com/datasheet/SiT8009
LB16-LB27 = LB_Inductor: 220 Ohms @ 100 MHz 1 Power Line Ferrite Bead 0603 (1608 Metric) 2.2A 50mOhm; Current: 2.2A; DCR: 50mohm; Manufacturer: Murata Electronics
U3 = LIFCL-17-CABGA256_0
C235 C237 C238 C332 = CAP_NP: 22 µF ±20% 25V Ceramic Capacitor X5R 0805 (2012 Metric); Manufacturer: TDK Corporation; Manufacturer Part Number: C2012X5R1E226M125AC; Part Number: C2012X5R1E226M125AC; Part type: Ceramic; Tolerance: 20%; Voltage: 25V
J1 = ASP-134486-01: 400 Position Connector Array, Female Sockets Surface Mount Gold; Manufacturer: Samtec; Part Type: Connector; Datasheet: https://suddendocs.samtec.com/prints/asp-134486-01-mkt.pdf?_gl=1*11mbaqs*_ga*MTcwNTM0ODkyOC4xNjc2MzAzMTU3*_ga_3KFNZC07WW*MTY3NjMyMjUxNS4yLjEuMTY3NjMyMjkxOC4yOS4wLjA.
TP8 TP18-TP20 = TP1: Test Point 0.39"; Manufacturer: NA; Part Type: Test Point; Datasheet: NA
J16-J19 = SMP-PLUG: CONN SMP PLUG STR 50 OHM SMD; Manufacturer: Molex; Part Type: Connector; Datasheet: https://www.molex.com/en-us/products/part-detail/853050232?display=pdf
R167 = R: RES 0402 100kohm 1% 62.5mW; Manufacturer: Matsushita Electric Works, Ltd.; Manufacturer Part Number: ERJ2RKF1003X; Part Number: ERJ2RKF1003X; Part type: Thick Film; Power: 62.5mW; Tolerance: 1%
U20 U21 = 74LVC1T45: Voltage Level Translator Bidirectional 1 Circuit 1 Channel 420Mbps 6-TSSOP; Manufacturer: Nexperia; Part Type: Level Translator; Datasheet: https://assets.nexperia.com/documents/data-sheet/74LVC_LVCH1T45.pdf
C228 = CAP_NP: 10 µF ±10% 10V Ceramic Capacitor X7R 0805 (2012 Metric); Manufacturer: Murata; Manufacturer Part Number: GRM21BR71A106KA73K; Part Number: GRM21BR71A106KA73K; Part type: Ceramic; Tolerance: 10%; Voltage: 10V; Datasheet: https://search.murata.co.jp/Ceramy/image/img/A01X/G101/ENG/GRM21BR71A106KA73-01.pdf
C236 = CAP_NP: CAP NCS X5R 0805 22uF +/-20% 6.3V; Manufacturer: Yageo Corporation; Manufacturer Part Number: CC0805MKX5R5BB226; Part Number: CC0805MKX5R5BB226; Part type: Ceramic; Tolerance: 20%; Voltage: 6.3V
C240 = CAP_NP: CAP NCS X7R 0402 0.1uF 10% 16V; Manufacturer: KEMET Corporation; Manufacturer Part Number: C0402C104K4RACTU; Part Number: C0402C104K4RACTU; Part type: Ceramic; Tolerance: 10%; Voltage: 16V; Datasheet: https://content.kemet.com/datasheets/KEM_C1002_X7R_SMD.pdf
J2 J4 = 2007198-1: Position SFP+ Cage Connector Press-Fit Through Hole, Right Angle; Manufacturer: TE Connectivity Ltd.; Part Type: Connector; Datasheet: https://www.te.com/commerce/DocumentDelivery/DDEController?Action=srchrtrv&DocNm=4-1773449-5&DocType=DS&DocLang=English
J3 J5 = 1888247-1: 20 Position SFP+ Receptacle Connector Solder Surface Mount, Right Angle; Manufacturer: TE Connectivity Ltd.; Part Type: Connector; Datasheet: https://www.te.com/commerce/DocumentDelivery/DDEController?Action=srchrtrv&DocNm=4-1773449-5&DocType=DS&DocLang=English

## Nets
GND: C1.2 C2.2 C3.2 C4.2 C5.2 C7.2 C165.2 C167.2 C168.2 C169.2 C170.2 C171.2 C172.2 C173.2 C174.2 C175.2 C176.2 C177.2 C178.2 C179.2 C180.2 C181.2 C182.2 C183.2 C184.2 C185.2 C186.2 C187.2 C188.2 C189.2 C190.2 C197.2 C198.2 C199.2 C200.2 C201.2 C202.2 C203.2 C204.2 C205.2 C206.2 C207.2 C208.2 C209.2 C210.2 C211.2 C212.2 C213.2 C214.2 C215.2 C216.2 C217.2 C218.2 C219.2 C220.2 C221.2 C222.2 C223.2 C224.2 C227.2 C228.2 C229.2 C230.2 C231.2 C232.2 C233.2 C234.2 C235.2 C236.2 C237.2 C238.2 C239.2 C240.2 C241.2 C242.2 C243.2 C244.2 C331.2 C332.2 C333.2 C336.2 C337.2 J1.A1(GND) J1.A4(GND) J1.A5(GND) J1.A8(GND) J1.A9(GND) J1.A12(GND) J1.A13(GND) J1.A16(GND) J1.A17(GND) J1.A20(GND) J1.A21(GND) J1.A24(GND) J1.A25(GND) J1.A28(GND) J1.A29(GND) J1.A32(GND) J1.A33(GND) J1.A36(GND) J1.A37(GND) J1.A40(GND) J1.B2(GND) J1.B3(GND) J1.B6(GND) J1.B7(GND) J1.B10(GND) J1.B11(GND) J1.B14(GND) J1.B15(GND) J1.B18(GND) J1.B19(GND) J1.B22(GND) J1.B23(GND) J1.B26(GND) J1.B27(GND) J1.B30(GND) J1.B31(GND) J1.B34(GND) J1.B35(GND) J1.B38(GND) J1.B39(GND) J1.C1(GND) J1.C4(GND) J1.C5(GND) J1.C8(GND) J1.C9(GND) J1.C12(GND) J1.C13(GND) J1.C16(GND) J1.C17(GND) J1.C20(GND) J1.C21(GND) J1.C24(GND) J1.C25(GND) J1.C28(GND) J1.C29(GND) J1.C32(GND) J1.C33(GND) J1.C36(GND) J1.C38(GND) J1.C40(GND) J1.D2(GND) J1.D3(GND) J1.D6(GND) J1.D7(GND) J1.D10(GND) J1.D13(GND) J1.D16(GND) J1.D19(GND) J1.D22(GND) J1.D25(GND) J1.D28(GND) J1.D37(GND) J1.D39(GND) J1.E1(GND) J1.E4(GND) J1.E5(GND) J1.E8(GND) J1.E11(GND) J1.E14(GND) J1.E17(GND) J1.E20(GND) J1.E23(GND) J1.E26(GND) J1.E29(GND) J1.E32(GND) J1.E35(GND) J1.E38(GND) J1.E40(GND) J1.F2(GND) J1.F3(GND) J1.F6(GND) J1.F9(GND) J1.F12(GND) J1.F15(GND) J1.F18(GND) J1.F21(GND) J1.F24(GND) J1.F27(GND) J1.F30(GND) J1.F33(GND) J1.F36(GND) J1.F39(GND) J1.G1(GND) J1.G4(GND) J1.G5(GND) J1.G8(GND) J1.G11(GND) J1.G14(GND) J1.G17(GND) J1.G20(GND) J1.G23(GND) J1.G26(GND) J1.G29(GND) J1.G32(GND) J1.G35(GND) J1.G38(GND) J1.G40(GND) J1.H3(GND) J1.H6(GND) J1.H9(GND) J1.H12(GND) J1.H15(GND) J1.H18(GND) J1.H21(GND) J1.H24(GND) J1.H27(GND) J1.H30(GND) J1.H33(GND) J1.H36(GND) J1.H39(GND) J1.J1(GND) J1.J4(GND) J1.J5(GND) J1.J8(GND) J1.J11(GND) J1.J14(GND) J1.J17(GND) J1.J20(GND) J1.J23(GND) J1.J26(GND) J1.J29(GND) J1.J32(GND) J1.J35(GND) J1.J38(GND) J1.J40(GND) J1.K2(GND) J1.K3(GND) J1.K6(GND) J1.K9(GND) J1.K12(GND) J1.K15(GND) J1.K18(GND) J1.K21(GND) J1.K24(GND) J1.K27(GND) J1.K30(GND) J1.K33(GND) J1.K36(GND) J1.K39(GND) J2.1(GND) J2.2(GND) J2.3(GND) J2.4(GND) J2.5(GND) J2.6(GND) J2.7(GND) J2.8(GND) J2.9(GND) J2.10(GND) J2.11(GND) J2.12(GND) J2.13(GND) J2.14(GND) J2.15(GND) J2.16(GND) J2.17(GND) J2.18(GND) J2.19(GND) J2.20(GND) J3.1(VEET-2) J3.10(VEER-2) J3.11(VEER-3) J3.14(VEER-1) J3.17(VEET-1) J3.20(VEET-3) J4.1(GND) J4.2(GND) J4.3(GND) J4.4(GND) J4.5(GND) J4.6(GND) J4.7(GND) J4.8(GND) J4.9(GND) J4.10(GND) J4.11(GND) J4.12(GND) J4.13(GND) J4.14(GND) J4.15(GND) J4.16(GND) J4.17(GND) J4.18(GND) J4.19(GND) J4.20(GND) J5.1(VEET-2) J5.10(VEER-2) J5.11(VEER-3) J5.14(VEER-1) J5.17(VEET-1) J5.20(VEET-3) J9.5 J9.6 J9.11 J9.12 J9.17 J9.18 J9.23 J9.24 J9.29 J9.30 J9.35 J9.36 J9.41 J9.42 J9.47 J9.48 J9.53 J9.54 J9.63 J9.64 J9.69 J9.70 J9.79 J9.80 J9.99 J9.100 J9.115 J9.116 J9.121 J9.122 J9.123 J9.124 J9.125 J9.126 J9.127 J9.128 J16.2(GND) J17.2(GND) J18.2(GND) J19.2(GND) Q6.2(SOURCE) Q7.1(S1) Q7.4(S2) Q8.1(S1) Q8.4(S2) Q9.1(S1) Q9.4(S2) R23.2 R25.2 R29.2 R31.2 R160.2 R167.2 R205.1 U3.A1(VSSADPHY) U3.A8(VSSADPHY) U3.A10(NC) U3.A13(NC) U3.A16(NC) U3.B8(VSSADPHY) U3.B10(NC) U3.B14(NC) U3.C3(VSSADPHY) U3.C6(VSSADPHY) U3.C9(VSS) U3.C10(VSS) U3.D3(VSSADPHY) U3.D8(VSS) U3.D14(VSS) U3.E7(VSS) U3.E8(VSS) U3.F3(VSSADPHY) U3.F12(VSS) U3.G1(VSSADPHY) U3.G2(VSS) U3.G5(NC) U3.G8(VSS) U3.H8(VSS) U3.H9(VSS) U3.J3(NC) U3.J7(VSS) U3.J8(VSS) U3.J9(VSS) U3.J14(VSS) U3.L13(VSSADC) U3.M5(VSS) U3.N7(VSS) U3.P13(VSS) U3.T1(VSS) U3.T16(VSS) U9.4(GND) U9.9(EPAD) U20.2(GND) U20.5(DIR) U21.2(GND) U21.5(DIR) Y3.2(GND) ; also on sheet 4 5 6 7 8 16 17 18 19
VDD_1V0: C209.1 C210.1 C211.1 C212.1 C213.1 C214.1 C215.1 U3.D7(VCC) U3.D9(VCC) U3.H7(VCC) U3.J10(VCC) U3.K9(VCC) ; also on sheet 8 18
VDD_1V0_CLNK_VCCDPHY0: C198.1 C204.1 LB17.2 U3.C4(VCCDPHY0)
VDD_1V0_CLNK_VCCDPHY1: C201.1 C207.1 LB20.2 U3.C7(VCCDPHY1)
VDD_1V0_CLNK_VCCPLLDPHY0: C199.1 C205.1 LB18.2 U3.A2(VCCPLLDPHY0)
VDD_1V0_CLNK_VCCPLLDPHY1: C202.1 C208.1 LB21.2 U3.C5(VCCPLLDPHY1)
VDD_1V0_LDO: LB17.1 LB18.1 LB20.1 LB21.1 ; also on sheet 7 19
VDD_1V8: C165.1 C167.1 C168.1 C169.1 C170.1 C171.1 C172.1 C173.1 C174.1 C175.1 C176.1 C177.1 C178.1 C179.1 C180.1 C181.1 C182.1 C183.1 C184.1 C185.1 C186.1 C187.1 C188.1 C189.1 C190.1 C333.1 C336.1 J1.E39(VADJ) J1.F40(VADJ) J1.G39(VADJ) J1.H40(VADJ) LB22.2 LB23.2 Q10.2(G1) Q10.5(G2) Q11.1(GATE) R2.1 R129.1 R131.1 R132.1 R136.1 R140.1 R155.2 R156.2 R161.1 R169.1 R185.1 U3.D13(VCCIO0) U3.F5(NC) U3.F13(VCCIO1) U3.J4(NC) U3.J13(NC) U3.N5(VCCIO5) U3.N6(VCCIO4) U3.P12(VCCIO3) U9.8(VCC) U20.6(VCCb) U21.6(VCCb) ; also on sheet 4 5 6 16 17 18 19
VDD_1V8_CAM: C4.1 J9.102 ; also on sheet 6 19
VDD_1V8_CLNK_CLK: C7.1 R185.2 Y3.4(VCC)
VDD_1V8_CLNK_VCCADPHY0: C197.1 C203.1 LB16.2 U3.E3(VCCADPHY0)
VDD_1V8_CLNK_VCCADPHY1: C200.1 C206.1 LB19.2 U3.C8(VCCADPHY1)
VDD_1V8_LDO: LB16.1 LB19.1 ; also on sheet 6 7 8 19
VDD_2V8_LDO: J9.81 J9.82 J9.83 ; also on sheet 19
VDD_3V3: C227.1 C228.1 C229.1 C230.1 C231.1 C232.1 C233.1 C234.1 C331.1 C337.1 DS2.2(ANODE) DS4.2(ANODE) J1.C39(3P3V) J1.D32(3P3VAUX) J1.D36(3P3V) J1.D38(3P3V) J1.D40(3P3V) LB24.1 LB25.1 LB26.1 LB27.1 R18.2 R19.2 R20.2 R21.2 R22.2 R24.2 R26.2 R27.2 R28.2 R30.2 R32.2 R33.2 R34.2 R35.2 R36.2 R37.2 R137.2 R138.2 R139.1 R146.1 R147.1 R170.1 U20.1(VCCa) U21.1(VCCa) ; also on sheet 4 6 16 17 18 19
VDD_3V3_CAM: C1.1 C2.1 C3.1 C5.1 J9.108 J9.110 J9.118 J9.120 ; also on sheet 19
VDD_3V3_SFP0_VCCR: C235.1 C239.1 C243.1 J3.15(VCCR) LB24.2
VDD_3V3_SFP0_VCCT: C236.1 C240.1 J3.16(VCCT) LB25.2
VDD_3V3_SFP1_VCCR: C237.1 C241.1 C244.1 J5.15(VCCR) LB26.2
VDD_3V3_SFP1_VCCT: C238.1 C242.1 J5.16(VCCT) LB27.2
VDD_12V: C332.1 J1.C35(12P0V) J1.C37(12P0V) ; also on sheet 18 19
CAM_MCLK_0: J9.91 ; also on sheet 16
CAM_MCLK_1: J9.88 ; also on sheet 16
CAM_MCLK_2: J9.94 ; also on sheet 16
CLNK_DONE: Q6.1(GATE) R129.2 U3.B16(PT59B/DONE)
CLNK_DONE_N_LED: DS4.1(CATHODE) R133.1
CLNK_DONE_N_LED_R: Q6.3(DRAIN) R133.2
CLNK_FLASH_QSPI_MCS_N: U3.C15(PT61A/MCSN/PCLKT0_1) U9.1(*CS)
CLNK_FLASH_QSPI_MD0: U3.C14(PT61B/MOSI/MD0) U9.5(DI(IO0))
CLNK_FLASH_QSPI_MD1: U3.D16(PT63A/MISO/MD1) U9.2(DO(IO1))
CLNK_FLASH_QSPI_MD2: R205.2 U3.D15(PT63B/MD2) U9.3(*WP(IO2))
CLNK_FLASH_QSPI_MD3: U3.D12(PT65A/MD3) U9.7(*HOLD(IO3))
CLNK_FLASH_QSPI_MSCK: R81.1 R160.1 R161.2 U3.C16(PT59A/MCLK/PCLKT0_0)
CLNK_FLASH_QSPI_MSCK_R: R81.2 U9.6(CLK)
CLNK_INIT: Q7.5(G2) Q7.6(D1) R132.2
CLNK_INIT_N: Q7.2(G1) R131.2 U3.D11(PT57A/INITN)
CLNK_INIT_N_LED: DS2.1(CATHODE) R130.1
CLNK_INIT_N_LED_R: Q7.3(D2) R130.2
CLNK_JTAG_TDI: U3.F11(PR5A/TDI/SSI) ; also on sheet 17
CLNK_JTAG_TDO: U3.E14(PR5B/TDO/SSO) ; also on sheet 17
CLNK_LVDS_0_N: U3.M15(PB70B/LRC_GPLL0C_IN/VREF3_2) ; also on sheet 5
CLNK_LVDS_0_P: U3.M16(PB70A/LRC_GPLL0T_IN) ; also on sheet 5
CLNK_LVDS_1_N: U3.R10(PB58B/ADC_CN7) ; also on sheet 5
CLNK_LVDS_1_P: U3.P10(PB58A/ADC_CP7) ; also on sheet 5
CLNK_LVDS_2_N: U3.T13(PB62B/ADC_CN9) ; also on sheet 5
CLNK_LVDS_2_P: U3.R12(PB62A/ADC_CP9) ; also on sheet 5
CLNK_LVDS_3_N: U3.R15(PB64B/ADC_CN8) ; also on sheet 5
CLNK_LVDS_3_P: U3.R16(PB64A/ADC_CP8) ; also on sheet 5
CLNK_LVDS_4_N: U3.P5(PB46B) ; also on sheet 5
CLNK_LVDS_4_P: U3.R5(PB46A) ; also on sheet 5
CLNK_LVDS_5_N: U3.P7(PB50B) ; also on sheet 5
CLNK_LVDS_5_P: U3.P6(PB50A) ; also on sheet 5
CLNK_LVDS_6_N: U3.R2(PB40B) ; also on sheet 5
CLNK_LVDS_6_P: U3.R1(PB40A/VREF4_1) ; also on sheet 5
CLNK_LVDS_7_N: U3.T4(PB44B) ; also on sheet 5
CLNK_LVDS_7_P: U3.T3(PB44A) ; also on sheet 5
CLNK_LVDS_8_N: U3.N3(PB16B/CDR_RXN0/ADC_CN0/COMP1N) ; also on sheet 5
CLNK_LVDS_8_P: U3.P3(PB16A/CDR_RXP0/VREF5_1/ADC_CP0/COMP1P) ; also on sheet 5
CLNK_LVDS_9_N: U3.L3(PB24B) ; also on sheet 5
CLNK_LVDS_9_P: U3.M3(PB24A) ; also on sheet 5
CLNK_LVDS_10_N: U3.L5(PB22B) ; also on sheet 5
CLNK_LVDS_10_P: U3.L4(PB22A) ; also on sheet 5
CLNK_LVDS_11_N: U3.N1(PB28B) ; also on sheet 5
CLNK_LVDS_11_P: U3.N2(PB28A) ; also on sheet 5
CLNK_LVDS_CC_0_N: U3.N14(PB68B/PCLKC3_3/ADC_CN14) ; also on sheet 5
CLNK_LVDS_CC_0_P: U3.M14(PB68A/PCLKT3_3/ADC_CP14) ; also on sheet 5
CLNK_LVDS_CC_1_N: U3.P11(PB56B/PCLKC3_0/ADC_CN5) ; also on sheet 5
CLNK_LVDS_CC_1_P: U3.R11(PB56A/PCLKT3_0/VREF3_1/ADC_CP5) ; also on sheet 5
CLNK_LVDS_CC_2_N: U3.P16(PB66B/PCLKC3_2/ADC_CN13) ; also on sheet 5
CLNK_LVDS_CC_2_P: U3.P15(PB66A/PCLKT3_2/ADC_CP13) ; also on sheet 5
CLNK_LVDS_CC_3_N: U3.T11(PB60B/PCLKC3_1/ADC_CN6) ; also on sheet 5
CLNK_LVDS_CC_3_P: U3.T12(PB60A/PCLKT3_1/ADC_CP6) ; also on sheet 5
CLNK_LVDS_CC_4_N: U3.P4(PB48B/PCLKC4_2) ; also on sheet 5
CLNK_LVDS_CC_4_P: U3.R4(PB48A/PCLKT4_2) ; also on sheet 5
CLNK_LVDS_CC_5_N: U3.P9(PB54B/PCLKC4_0/VREF4_2) ; also on sheet 5
CLNK_LVDS_CC_5_P: U3.R9(PB54A/PCLKT4_0) ; also on sheet 5
CLNK_LVDS_CC_6_N: U3.T2(PB42B/PCLKC4_3) ; also on sheet 5
CLNK_LVDS_CC_6_P: U3.R3(PB42A/PCLKT4_3) ; also on sheet 5
CLNK_LVDS_CC_7_N: U3.T10(PB52B/PCLKC4_1) ; also on sheet 5
CLNK_LVDS_CC_7_P: U3.T9(PB52A/PCLKT4_1) ; also on sheet 5
CLNK_LVDS_CC_8_N: U3.K7(PB26B/PCLKC5_2/CDR0_TESTN/ADC_CN2/COMP3N) ; also on sheet 5
CLNK_LVDS_CC_8_P: U3.L6(PB26A/PCLKT5_2/CDR0_TESTP/ADC_CP2/COMP3P) ; also on sheet 5
CLNK_LVDS_CC_9_N: U3.M4(PB18B/PCLKC5_0/CDR_RXN1/ADC_CN1/COMP2N) ; also on sheet 5
CLNK_LVDS_CC_9_P: U3.N4(PB18A/PCLKT5_0/CDR_RXP1/ADC_CP1/COMP2P) ; also on sheet 5
CLNK_LVDS_CC_10_N: U3.P2(PB30B/PCLKC5_3/VREF5_2) ; also on sheet 5
CLNK_LVDS_CC_10_P: U3.P1(PB30A/PCLKT5_3) ; also on sheet 5
CLNK_LVDS_CC_11_N: U3.M7(PB20B/PCLKC5_1/LLC_GPLL0C_IN/ADC_CN3) ; also on sheet 5
CLNK_LVDS_CC_11_P: U3.L7(PB20A/PCLKT5_1/LLC_GPLL0T_IN/ADC_CP3) ; also on sheet 5
CLNK_PCLK: R3.2 U3.F16(PR13A/PCLKT1_1)
CLNK_PCLK_EN: R2.2 Y3.1(EN)
CLNK_PCLK_R: R3.1 Y3.3(OUT)
CPCL_GPIO_0: U3.E15(PT67A) ; also on sheet 4
CPCL_GPIO_1: U3.E16(PT67B) ; also on sheet 4
CPRO_CAM_GPIO_0: J9.76 ; also on sheet 6
CPRO_CAM_GPIO_1: J9.78 ; also on sheet 6
CPRO_CAM_GPIO_2: J9.84 ; also on sheet 6
CPRO_CAM_GPIO_3: J9.85 ; also on sheet 6
CPRO_CAM_GPIO_4: J9.90 ; also on sheet 6
CPRO_CAM_GPIO_5: J9.92 ; also on sheet 6
CPRO_CAM_GPIO_6: J9.96 ; also on sheet 6
CPRO_CAM_GPIO_7: J9.97 ; also on sheet 6
CPRO_CAM_GPIO_8: J9.98 ; also on sheet 6
CPRO_CAM_GPIO_9: J9.119 ; also on sheet 6
CPRO_CAM_I2C0_SCL: J9.75 ; also on sheet 6
CPRO_CAM_I2C0_SDA: J9.77 ; also on sheet 6
CPRO_CAM_I2C1_SCL: J9.87 ; also on sheet 6
CPRO_CAM_I2C1_SDA: J9.89 ; also on sheet 6
CPRO_CAM_I2C2_SCL: J9.105 ; also on sheet 6
CPRO_CAM_I2C2_SDA (page 12-Camera Connector Interface): J9.107
CPRO_CAM_SPI_MCS_N: J9.104 ; also on sheet 6
CPRO_CAM_SPI_MISO: J9.106 ; also on sheet 6
CPRO_CAM_SPI_MOSI: J9.103 ; also on sheet 6
CPRO_CAM_SPI_MSCK: J9.117 ; also on sheet 6
CPRO_CAM_UART_CTS: J9.93 ; also on sheet 6
CPRO_CAM_UART_RTS: J9.86 ; also on sheet 6
CPRO_CAM_UART_TX: J9.95 ; also on sheet 6
CPRO_CTRL_SPI_MCLK: U3.G13(PR11B/PCLKT1_2) ; also on sheet 4
CPRO_CTRL_SPI_MCS_N: U3.C13(PT65B/MCSNO/MSDO) ; also on sheet 4
CPRO_CTRL_SPI_MISO: U3.G11(PR11A) ; also on sheet 4
CPRO_CTRL_SPI_MOSI: U3.G15(PR13B/PCLKT1_0) ; also on sheet 4
CPRO_FMC_CLK0_M2C_N: J1.H5(CLK0_M2C_N) ; also on sheet 5
CPRO_FMC_CLK0_M2C_P: J1.H4(CLK0_M2C_P) ; also on sheet 5
CPRO_FMC_CLK1_M2C_N: J1.G3(CLK1_M2C_N) ; also on sheet 5
CPRO_FMC_CLK1_M2C_P: J1.G2(CLK1_M2C_P) ; also on sheet 5
CPRO_FMC_CLK3_BIDIR_N: J1.J3(CLK3_M2C_N) ; also on sheet 5
CPRO_FMC_CLK3_BIDIR_P: J1.J2(CLK3_M2C_P) ; also on sheet 5
CPRO_FMC_CLK_DIR: J1.B1(RES1) Q11.3(DRAIN) R167.1
CPRO_FMC_CLK_DIR_1V8: Q11.2(SOURCE) R169.2 ; also on sheet 5
CPRO_FMC_GA0: J1.C34(GA0) U20.3(A)
CPRO_FMC_GA0_1V8: U20.4(B) ; also on sheet 5
CPRO_FMC_GA1: J1.D35(GA1) U21.3(A)
CPRO_FMC_GA1_1V8: U21.4(B) ; also on sheet 5
CPRO_FMC_GBTCLK0_N: J1.D5(GBTCLK0_M2C_N) ; also on sheet 7
CPRO_FMC_GBTCLK0_P: J1.D4(GBTCLK0_M2C_P) ; also on sheet 7
CPRO_FMC_GBTCLK1_N: J1.B21(GBTCLK1_M2C_N) ; also on sheet 7
CPRO_FMC_GBTCLK1_P: J1.B20(GBTCLK1_M2C_P) ; also on sheet 7
CPRO_FMC_I2C_SCL: J1.C30(SCL) Q10.6(D1) R138.1
CPRO_FMC_I2C_SCL_1V8: Q10.1(S1) R156.1 ; also on sheet 5
CPRO_FMC_I2C_SDA: J1.C31(SDA) Q10.3(D2) R137.1
CPRO_FMC_I2C_SDA_1V8: Q10.4(S2) R155.1 ; also on sheet 5
CPRO_FMC_LA00_CC_N: J1.G7(LA00_N_CC) ; also on sheet 5
CPRO_FMC_LA00_CC_P: J1.G6(LA00_P_CC) ; also on sheet 5
CPRO_FMC_LA01_CC_N: J1.D9(LA01_N_CC) ; also on sheet 5
CPRO_FMC_LA01_CC_P: J1.D8(LA01_P_CC) ; also on sheet 5
CPRO_FMC_LA02_N: J1.H8(LA02_N) ; also on sheet 5
CPRO_FMC_LA02_P: J1.H7(LA02_P) ; also on sheet 5
CPRO_FMC_LA03_N: J1.G10(LA03_N) ; also on sheet 5
CPRO_FMC_LA03_P: J1.G9(LA03_P) ; also on sheet 5
CPRO_FMC_LA04_N: J1.H11(LA04_N) ; also on sheet 5
CPRO_FMC_LA04_P: J1.H10(LA04_P) ; also on sheet 5
CPRO_FMC_LA05_N: J1.D12(LA05_N) ; also on sheet 5
CPRO_FMC_LA05_P: J1.D11(LA05_P) ; also on sheet 5
CPRO_FMC_LA06_N: J1.C11(LA06_N) ; also on sheet 5
CPRO_FMC_LA06_P: J1.C10(LA06_P) ; also on sheet 5
CPRO_FMC_LA07_N: J1.H14(LA07_N) ; also on sheet 5
CPRO_FMC_LA07_P: J1.H13(LA07_P) ; also on sheet 5
CPRO_FMC_LA08_N: J1.G13(LA08_N) ; also on sheet 5
CPRO_FMC_LA08_P: J1.G12(LA08_P) ; also on sheet 5
CPRO_FMC_LA09_N: J1.D15(LA09_N) ; also on sheet 5
CPRO_FMC_LA09_P: J1.D14(LA09_P) ; also on sheet 5
CPRO_FMC_LA10_N: J1.C15(LA10_N) ; also on sheet 5
CPRO_FMC_LA10_P: J1.C14(LA10_P) ; also on sheet 5
CPRO_FMC_LA11_N: J1.H17(LA11_N) ; also on sheet 5
CPRO_FMC_LA11_P: J1.H16(LA11_P) ; also on sheet 5
CPRO_FMC_LA12_N: J1.G16(LA12_N) ; also on sheet 5
CPRO_FMC_LA12_P: J1.G15(LA12_P) ; also on sheet 5
CPRO_FMC_LA13_N: J1.D18(LA13_N) ; also on sheet 5
CPRO_FMC_LA13_P: J1.D17(LA13_P) ; also on sheet 5
CPRO_FMC_LA14_N: J1.C19(LA14_N) ; also on sheet 5
CPRO_FMC_LA14_P: J1.C18(LA14_P) ; also on sheet 5
CPRO_FMC_LA15_N: J1.H20(LA15_N) ; also on sheet 5
CPRO_FMC_LA15_P: J1.H19(LA15_P) ; also on sheet 5
CPRO_FMC_LA16_N: J1.G19(LA16_N) ; also on sheet 5
CPRO_FMC_LA16_P: J1.G18(LA16_P) ; also on sheet 5
CPRO_FMC_LA17_N: J1.D21(LA17_N_CC) ; also on sheet 5
CPRO_FMC_LA17_P: J1.D20(LA17_P_CC) ; also on sheet 5
CPRO_FMC_LA18_N: J1.C23(LA18_N_CC) ; also on sheet 5
CPRO_FMC_LA18_P: J1.C22(LA18_P_CC) ; also on sheet 5
CPRO_FMC_LA19_N: J1.H23(LA19_N) ; also on sheet 5
CPRO_FMC_LA19_P: J1.H22(LA19_P) ; also on sheet 5
CPRO_FMC_LA20_N: J1.G22(LA20_N) ; also on sheet 5
CPRO_FMC_LA20_P: J1.G21(LA20_P) ; also on sheet 5
CPRO_FMC_LA21_N: J1.H26(LA21_N) ; also on sheet 5
CPRO_FMC_LA21_P: J1.H25(LA21_P) ; also on sheet 5
CPRO_FMC_LA22_N: J1.G25(LA22_N) ; also on sheet 5
CPRO_FMC_LA22_P: J1.G24(LA22_P) ; also on sheet 5
CPRO_FMC_LA23_N: J1.D24(LA23_N) ; also on sheet 5
CPRO_FMC_LA23_P: J1.D23(LA23_P) ; also on sheet 5
CPRO_FMC_LA24_N: J1.H29(LA24_N) ; also on sheet 5
CPRO_FMC_LA24_P: J1.H28(LA24_P) ; also on sheet 5
CPRO_FMC_LA25_N: J1.G28(LA25_N) ; also on sheet 5
CPRO_FMC_LA25_P: J1.G27(LA25_P) ; also on sheet 5
CPRO_FMC_LA26_N: J1.D27(LA26_N) ; also on sheet 5
CPRO_FMC_LA26_P: J1.D26(LA26_P) ; also on sheet 5
CPRO_FMC_LA27_N: J1.C27(LA27_N) ; also on sheet 5
CPRO_FMC_LA27_P: J1.C26(LA27_P) ; also on sheet 5
CPRO_FMC_LA28_N: J1.H32(LA28_N) ; also on sheet 5
CPRO_FMC_LA28_P: J1.H31(LA28_P) ; also on sheet 5
CPRO_FMC_LA29_N: J1.G31(LA29_N) ; also on sheet 5
CPRO_FMC_LA29_P: J1.G30(LA29_P) ; also on sheet 5
CPRO_FMC_LA30_N: J1.H35(LA30_N) ; also on sheet 5
CPRO_FMC_LA30_P: J1.H34(LA30_P) ; also on sheet 5
CPRO_FMC_LA31_N: J1.G34(LA31_N) ; also on sheet 5
CPRO_FMC_LA31_P: J1.G33(LA31_P) ; also on sheet 5
CPRO_FMC_LA32_N: J1.H38(LA32_N) ; also on sheet 5
CPRO_FMC_LA32_P: J1.H37(LA32_P) ; also on sheet 5
CPRO_FMC_LA33_N: J1.G37(LA33_N) ; also on sheet 5
CPRO_FMC_LA33_P: J1.G36(LA33_P) ; also on sheet 5
CPRO_FMC_PG_M2C_1V8: Q9.3(D2) R140.2 ; also on sheet 5
CPRO_FMC_PRSNT_N: J1.H2(PRSNT_M2C_L) R136.2 ; also on sheet 5
CPRO_FPGA_SYNC_IN: J17.1 ; also on sheet 6
CPRO_FPGA_SYNC_OUT: J16.1 ; also on sheet 6
CPRO_JESD_SYSREF_N: J18.1 ; also on sheet 5
CPRO_JESD_SYSREF_P: J19.1 ; also on sheet 5
DPHY0_DATA0_N: J9.3 U3.E2(DPHY0_DN0)
DPHY0_DATA0_P: J9.1 U3.E1(DPHY0_DP0)
DPHY0_DATA1_N: J9.15 U3.C2(DPHY0_DN1)
DPHY0_DATA1_P: J9.13 U3.C1(DPHY0_DP1)
DPHY0_DATA2_N: J9.4 U3.F2(DPHY0_DN2)
DPHY0_DATA2_P: J9.2 U3.F1(DPHY0_DP2)
DPHY0_DATA3_N: J9.16 U3.B2(DPHY0_DN3)
DPHY0_DATA3_P: J9.14 U3.B1(DPHY0_DP3)
DPHY0_DCLK_N: J9.9 U3.D2(DPHY0_CKN)
DPHY0_DCLK_P: J9.7 U3.D1(DPHY0_CKP)
DPHY1_DATA0_N: J9.21 U3.B4(DPHY1_DN0)
DPHY1_DATA0_P: J9.19 U3.A4(DPHY1_DP0)
DPHY1_DATA1_N: J9.33 U3.B6(DPHY1_DN1)
DPHY1_DATA1_P: J9.31 U3.A6(DPHY1_DP1)
DPHY1_DATA2_N: J9.22 U3.B3(DPHY1_DN2)
DPHY1_DATA2_P: J9.20 U3.A3(DPHY1_DP2)
DPHY1_DATA3_N: J9.34 U3.B7(DPHY1_DN3)
DPHY1_DATA3_P: J9.32 U3.A7(DPHY1_DP3)
DPHY1_DCLK_N: J9.27 U3.B5(DPHY1_CKN)
DPHY1_DCLK_P: J9.25 U3.A5(DPHY1_CKP)
ETH_RXD0_N: J3.12(RD-) ; also on sheet 7
ETH_RXD0_P: J3.13(RD+) ; also on sheet 7
ETH_RXD1_N: J5.12(RD-) ; also on sheet 7
ETH_RXD1_P: J5.13(RD+) ; also on sheet 7
ETH_TXD0_N: J3.19(TD-) ; also on sheet 7
ETH_TXD0_P: J3.18(TD+) ; also on sheet 7
ETH_TXD1_N: J5.19(TD-) ; also on sheet 7
ETH_TXD1_P: J5.18(TD+) ; also on sheet 7
FMC_CLK2_C2M_N: J1.K5(CLK2_M2C_N) ; also on sheet 16
FMC_CLK2_C2M_P: J1.K4(CLK2_M2C_P) ; also on sheet 16
FMC_PG_C2M: J1.D1(PG_C2M) Q8.3(D2) R147.2
FMC_PG_M2C: J1.F1(PG_M2C) Q9.2(G1) R170.2
FMC_PG_M2C_N: Q9.5(G2) Q9.6(D1) R139.2
FPGA_JTAG_EN: U3.D10(JTAG_EN) ; also on sheet 4 17
FPGA_JTAG_TCLK: U3.F14(PR9A/TCK/SCLK) ; also on sheet 4 17
FPGA_JTAG_TMS: U3.E11(PR3B/TMS/SCSN) ; also on sheet 4 17
FPGA_PROG_I2C_SCL: U3.G10(PR7B/SCL) ; also on sheet 4 17
FPGA_PROG_I2C_SDA: U3.G9(PR7A/SDA) ; also on sheet 4 17
FPGA_PROGRAM_N: U3.C12(PT57B/PROGRAMN) ; also on sheet 4 17
FPGA_RESET_N: U3.F15(PR9B) ; also on sheet 4 17
JESD_RXD0_N: J1.C7(DP0_M2C_N) ; also on sheet 7
JESD_RXD0_P: J1.C6(DP0_M2C_P) ; also on sheet 7
JESD_RXD1_N: J1.A3(DP1_M2C_N) ; also on sheet 7
JESD_RXD1_P: J1.A2(DP1_M2C_P) ; also on sheet 7
JESD_RXD2_N: J1.A7(DP2_M2C_N) ; also on sheet 7
JESD_RXD2_P: J1.A6(DP2_M2C_P) ; also on sheet 7
JESD_RXD3_N: J1.A11(DP3_M2C_N) ; also on sheet 7
JESD_RXD3_P: J1.A10(DP3_M2C_P) ; also on sheet 7
JESD_TXD0_N: J1.C3(DP0_C2M_N) ; also on sheet 7
JESD_TXD0_P: J1.C2(DP0_C2M_P) ; also on sheet 7
JESD_TXD1_N: J1.A23(DP1_C2M_N) ; also on sheet 7
JESD_TXD1_P: J1.A22(DP1_C2M_P) ; also on sheet 7
JESD_TXD2_N: J1.A27(DP2_C2M_N) ; also on sheet 7
JESD_TXD2_P: J1.A26(DP2_C2M_P) ; also on sheet 7
JESD_TXD3_N: J1.A31(DP3_C2M_N) ; also on sheet 7
JESD_TXD3_P: J1.A30(DP3_C2M_P) ; also on sheet 7
PG_PS_3V3: Q8.2(G1) ; also on sheet 18
PG_PS_3V3_N: Q8.5(G2) Q8.6(D1) R146.2
SFP0_ABS: J3.6(MOD_ABS) R20.1 ; also on sheet 6
SFP0_I2C_SCL: J3.5(SCL) R26.1 ; also on sheet 6
SFP0_I2C_SDA: J3.4(SDA) R32.1 ; also on sheet 6
SFP0_LOS: J3.8(RX_LOS) R18.1 ; also on sheet 6
SFP0_RS0: J3.7(RS0) R28.1 R29.1
SFP0_RS1: J3.9(RS1) R22.1 R23.1
SFP0_TX_DISABLE: J3.3(TX_DISABLE) R34.1 ; also on sheet 6
SFP0_TX_FAULT: J3.2(TX_FAULT) R36.1 ; also on sheet 6
SFP1_ABS: J5.6(MOD_ABS) R21.1 ; also on sheet 6
SFP1_I2C_SCL: J5.5(SCL) R27.1 ; also on sheet 6
SFP1_I2C_SDA: J5.4(SDA) R33.1 ; also on sheet 6
SFP1_LOS: J5.8(RX_LOS) R19.1 ; also on sheet 6
SFP1_RS0: J5.7(RS0) R30.1 R31.1
SFP1_RS1: J5.9(RS1) R24.1 R25.1
SFP1_TX_DISABLE: J5.3(TX_DISABLE) R35.1 ; also on sheet 6
SFP1_TX_FAULT: J5.2(TX_FAULT) R37.1 ; also on sheet 6
SNN_CAM_8: J9.8
SNN_CAM_10: J9.10
SNN_CAM_26: J9.26
SNN_CAM_28: J9.28
SNN_CAM_37: J9.37
SNN_CAM_38: J9.38
SNN_CAM_39: J9.39
SNN_CAM_40: J9.40
SNN_CAM_43: J9.43
SNN_CAM_44: J9.44
SNN_CAM_45: J9.45
SNN_CAM_46: J9.46
SNN_CAM_49: J9.49
SNN_CAM_50: J9.50
SNN_CAM_51: J9.51
SNN_CAM_52: J9.52
SNN_CAM_55: J9.55
SNN_CAM_56: J9.56
SNN_CAM_57: J9.57
SNN_CAM_58: J9.58
SNN_CAM_59: J9.59
SNN_CAM_60: J9.60
SNN_CAM_61: J9.61
SNN_CAM_62: J9.62
SNN_CAM_65: J9.65
SNN_CAM_66: J9.66
SNN_CAM_67: J9.67
SNN_CAM_68: J9.68
SNN_CAM_71: J9.71
SNN_CAM_72: J9.72
SNN_CAM_73: J9.73
SNN_CAM_74: J9.74
SNN_CAM_101: J9.101
SNN_CAM_109: J9.109
SNN_CAM_111: J9.111
SNN_CAM_112: J9.112
SNN_CAM_113: J9.113
SNN_CAM_114: J9.114
SNN_CLNK_ADC_DN0: U3.K13(ADC_DN0)
SNN_CLNK_ADC_DN1: U3.K16(ADC_DN1)
SNN_CLNK_ADC_DP0: U3.K14(ADC_DP0)
SNN_CLNK_ADC_DP1: U3.K15(ADC_DP1)
SNN_CLNK_ADC_REFP0: U3.L15(ADC_REFP0)
SNN_CLNK_ADC_REFP1: U3.L16(ADC_REFP1)
SNN_CLNK_NC_A9: U3.A9(NC)
SNN_CLNK_NC_A11: U3.A11(NC)
SNN_CLNK_NC_A12: U3.A12(NC)
SNN_CLNK_NC_A14: U3.A14(NC)
SNN_CLNK_NC_A15: U3.A15(NC)
SNN_CLNK_NC_B9: U3.B9(NC)
SNN_CLNK_NC_B11: U3.B11(NC)
SNN_CLNK_NC_B12: U3.B12(NC)
SNN_CLNK_NC_B13: U3.B13(NC)
SNN_CLNK_NC_B15: U3.B15(NC)
SNN_CLNK_NC_C11: U3.C11(NC)
SNN_CLNK_NC_D4: U3.D4(NC)
SNN_CLNK_NC_D5: U3.D5(NC)
SNN_CLNK_NC_D6: U3.D6(NC)
SNN_CLNK_NC_E4: U3.E4(NC)
SNN_CLNK_NC_E5: U3.E5(NC)
SNN_CLNK_NC_E6: U3.E6(NC)
SNN_CLNK_NC_E9: U3.E9(NC)
SNN_CLNK_NC_E10: U3.E10(NC)
SNN_CLNK_NC_E12: U3.E12(NC)
SNN_CLNK_NC_E13: U3.E13(NC)
SNN_CLNK_NC_F4: U3.F4(NC)
SNN_CLNK_NC_F6: U3.F6(NC)
SNN_CLNK_NC_F9: U3.F9(NC)
SNN_CLNK_NC_F10: U3.F10(NC)
SNN_CLNK_NC_G3: U3.G3(NC)
SNN_CLNK_NC_G4: U3.G4(NC)
SNN_CLNK_NC_G6: U3.G6(NC)
SNN_CLNK_NC_G12: U3.G12(NC)
SNN_CLNK_NC_G14: U3.G14(NC)
SNN_CLNK_NC_G16: U3.G16(NC)
SNN_CLNK_NC_H1: U3.H1(NC)
SNN_CLNK_NC_H2: U3.H2(NC)
SNN_CLNK_NC_H3: U3.H3(NC)
SNN_CLNK_NC_H4: U3.H4(NC)
SNN_CLNK_NC_H5: U3.H5(NC)
SNN_CLNK_NC_H6: U3.H6(NC)
SNN_CLNK_NC_H10: U3.H10(NC)
SNN_CLNK_NC_H11: U3.H11(NC)
SNN_CLNK_NC_H12: U3.H12(NC)
SNN_CLNK_NC_H13: U3.H13(NC)
SNN_CLNK_NC_H14: U3.H14(NC)
SNN_CLNK_NC_H15: U3.H15(NC)
SNN_CLNK_NC_H16: U3.H16(NC)
SNN_CLNK_NC_J1: U3.J1(NC)
SNN_CLNK_NC_J2: U3.J2(NC)
SNN_CLNK_NC_J5: U3.J5(NC)
SNN_CLNK_NC_J6: U3.J6(NC)
SNN_CLNK_NC_J11: U3.J11(NC)
SNN_CLNK_NC_J12: U3.J12(NC)
SNN_CLNK_NC_J15: U3.J15(NC)
SNN_CLNK_NC_J16: U3.J16(NC)
SNN_CLNK_NC_K1: U3.K1(NC)
SNN_CLNK_NC_K2: U3.K2(NC)
SNN_CLNK_NC_K3: U3.K3(NC)
SNN_CLNK_NC_K4: U3.K4(NC)
SNN_CLNK_NC_K5: U3.K5(NC)
SNN_CLNK_NC_K6: U3.K6(NC)
SNN_CLNK_NC_K11: U3.K11(NC)
SNN_CLNK_NC_K12: U3.K12(NC)
SNN_CLNK_NC_L1: U3.L1(NC)
SNN_CLNK_NC_L2: U3.L2(NC)
SNN_CLNK_NC_L8: U3.L8(NC)
SNN_CLNK_NC_L9: U3.L9(NC)
SNN_CLNK_NC_L10: U3.L10(NC)
SNN_CLNK_NC_L11: U3.L11(NC)
SNN_CLNK_NC_L12: U3.L12(NC)
SNN_CLNK_NC_M1: U3.M1(NC)
SNN_CLNK_NC_M2: U3.M2(NC)
SNN_CLNK_NC_M8: U3.M8(NC)
SNN_CLNK_NC_M9: U3.M9(NC)
SNN_CLNK_NC_M10: U3.M10(NC)
SNN_CLNK_NC_M11: U3.M11(NC)
SNN_CLNK_NC_M12: U3.M12(NC)
SNN_CLNK_NC_M13: U3.M13(NC)
SNN_CLNK_NC_N8: U3.N8(NC)
SNN_CLNK_NC_N9: U3.N9(NC)
SNN_CLNK_NC_N10: U3.N10(NC)
SNN_CLNK_NC_N11: U3.N11(NC)
SNN_CLNK_NC_N12: U3.N12(NC)
SNN_CLNK_NC_N13: U3.N13(NC)
SNN_CLNK_NC_N15: U3.N15(NC)
SNN_CLNK_NC_N16: U3.N16(NC)
SNN_CLNK_NC_P8: U3.P8(NC)
SNN_CLNK_NC_P14: U3.P14(NC)
SNN_CLNK_NC_R6: U3.R6(NC)
SNN_CLNK_NC_R7: U3.R7(NC)
SNN_CLNK_NC_R8: U3.R8(NC)
SNN_CLNK_NC_R13: U3.R13(NC)
SNN_CLNK_NC_R14: U3.R14(NC)
SNN_CLNK_NC_T5: U3.T5(NC)
SNN_CLNK_NC_T6: U3.T6(NC)
SNN_CLNK_NC_T7: U3.T7(NC)
SNN_CLNK_NC_T8: U3.T8(NC)
SNN_CLNK_NC_T14: U3.T14(NC)
SNN_CLNK_NC_T15: U3.T15(NC)
SNN_CLNK_VCCADC18: U3.L14(VCCADC18)
SNN_FMC_A14: J1.A14(DP4_M2C_P)
SNN_FMC_A15: J1.A15(DP4_M2C_N)
SNN_FMC_A18: J1.A18(DP5_M2C_P)
SNN_FMC_A19: J1.A19(DP5_M2C_N)
SNN_FMC_A34: J1.A34(DP4_C2M_P)
SNN_FMC_A35: J1.A35(DP4_C2M_N)
SNN_FMC_A38: J1.A38(DP5_C2M_P)
SNN_FMC_A39: J1.A39(DP5_C2M_N)
SNN_FMC_B4: J1.B4(DP9_M2C_P)
SNN_FMC_B5: J1.B5(DP9_M2C_N)
SNN_FMC_B8: J1.B8(DP8_M2C_P)
SNN_FMC_B9: J1.B9(DP8_M2C_N)
SNN_FMC_B12: J1.B12(DP7_M2C_P)
SNN_FMC_B13: J1.B13(DP7_M2C_N)
SNN_FMC_B16: J1.B16(DP6_M2C_P)
SNN_FMC_B17: J1.B17(DP6_M2C_N)
SNN_FMC_B24: J1.B24(DP9_C2M_P)
SNN_FMC_B25: J1.B25(DP9_C2M_N)
SNN_FMC_B28: J1.B28(DP8_C2M_P)
SNN_FMC_B29: J1.B29(DP8_C2M_N)
SNN_FMC_B32: J1.B32(DP7_C2M_P)
SNN_FMC_B33: J1.B33(DP7_C2M_N)
SNN_FMC_B36: J1.B36(DP6_C2M_P)
SNN_FMC_B37: J1.B37(DP6_C2M_N)
SNN_FMC_D29: J1.D29(TCK)
SNN_FMC_D30: J1.D30(TDI)
SNN_FMC_D31: J1.D31(TDO)
SNN_FMC_D33: J1.D33(TMS)
SNN_FMC_D34: J1.D34(TRST_L)
SNN_FMC_E2: J1.E2(HA01_P_CC)
SNN_FMC_E3: J1.E3(HA01_N_CC)
SNN_FMC_E6: J1.E6(HA05_P)
SNN_FMC_E7: J1.E7(HA05_N)
SNN_FMC_E9: J1.E9(HA09_P)
SNN_FMC_E10: J1.E10(HA09_N)
SNN_FMC_E12: J1.E12(HA13_P)
SNN_FMC_E13: J1.E13(HA13_N)
SNN_FMC_E15: J1.E15(HA16_P)
SNN_FMC_E16: J1.E16(HA16_N)
SNN_FMC_E18: J1.E18(HA20_P)
SNN_FMC_E19: J1.E19(HA20_N)
SNN_FMC_E21: J1.E21(HB03_P)
SNN_FMC_E22: J1.E22(HB03_N)
SNN_FMC_E24: J1.E24(HB05_P)
SNN_FMC_E25: J1.E25(HB05_N)
SNN_FMC_E27: J1.E27(HB09_P)
SNN_FMC_E28: J1.E28(HB09_N)
SNN_FMC_E30: J1.E30(HB13_P)
SNN_FMC_E31: J1.E31(HB13_N)
SNN_FMC_E33: J1.E33(HB19_P)
SNN_FMC_E34: J1.E34(HB19_N)
SNN_FMC_E36: J1.E36(HB21_P)
SNN_FMC_E37: J1.E37(HB21_N)
SNN_FMC_F4: J1.F4(HA00_P_CC)
SNN_FMC_F5: J1.F5(HA00_N_CC)
SNN_FMC_F7: J1.F7(HA04_P)
SNN_FMC_F8: J1.F8(HA04_N)
SNN_FMC_F10: J1.F10(HA08_P)
SNN_FMC_F11: J1.F11(HA08_N)
SNN_FMC_F13: J1.F13(HA12_P)
SNN_FMC_F14: J1.F14(HA12_N)
SNN_FMC_F16: J1.F16(HA15_P)
SNN_FMC_F17: J1.F17(HA15_N)
SNN_FMC_F19: J1.F19(HA19_P)
SNN_FMC_F20: J1.F20(HA19_N)
SNN_FMC_F22: J1.F22(HB02_P)
SNN_FMC_F23: J1.F23(HB02_N)
SNN_FMC_F25: J1.F25(HB04_P)
SNN_FMC_F26: J1.F26(HB04_N)
SNN_FMC_F28: J1.F28(HB08_P)
SNN_FMC_F29: J1.F29(HB08_N)
SNN_FMC_F31: J1.F31(HB12_P)
SNN_FMC_F32: J1.F32(HB12_N)
SNN_FMC_F34: J1.F34(HB16_P)
SNN_FMC_F35: J1.F35(HB16_N)
SNN_FMC_F37: J1.F37(HB20_P)
SNN_FMC_F38: J1.F38(HB20_N)
SNN_FMC_J6: J1.J6(HA03_P)
SNN_FMC_J7: J1.J7(HA03_N)
SNN_FMC_J9: J1.J9(HA07_P)
SNN_FMC_J10: J1.J10(HA07_N)
SNN_FMC_J12: J1.J12(HA11_P)
SNN_FMC_J13: J1.J13(HA11_N)
SNN_FMC_J15: J1.J15(HA14_P)
SNN_FMC_J16: J1.J16(HA14_N)
SNN_FMC_J18: J1.J18(HA18_P)
SNN_FMC_J19: J1.J19(HA18_N)
SNN_FMC_J21: J1.J21(HA22_P)
SNN_FMC_J22: J1.J22(HA22_N)
SNN_FMC_J24: J1.J24(HB01_P)
SNN_FMC_J25: J1.J25(HB01_N)
SNN_FMC_J27: J1.J27(HB07_P)
SNN_FMC_J28: J1.J28(HB07_N)
SNN_FMC_J30: J1.J30(HB11_P)
SNN_FMC_J31: J1.J31(HB11_N)
SNN_FMC_J33: J1.J33(HB15_P)
SNN_FMC_J34: J1.J34(HB15_N)
SNN_FMC_J36: J1.J36(HB18_P)
SNN_FMC_J37: J1.J37(HB18_N)
SNN_FMC_K7: J1.K7(HA02_P)
SNN_FMC_K8: J1.K8(HA02_N)
SNN_FMC_K10: J1.K10(HA06_P)
SNN_FMC_K11: J1.K11(HA06_N)
SNN_FMC_K13: J1.K13(HA10_P)
SNN_FMC_K14: J1.K14(HA10_N)
SNN_FMC_K16: J1.K16(HA17_P_CC)
SNN_FMC_K17: J1.K17(HA17_N_CC)
SNN_FMC_K19: J1.K19(HA21_P)
SNN_FMC_K20: J1.K20(HA21_N)
SNN_FMC_K22: J1.K22(HA23_P)
SNN_FMC_K23: J1.K23(HA23_N)
SNN_FMC_K25: J1.K25(HB00_P_CC)
SNN_FMC_K26: J1.K26(HB00_N_CC)
SNN_FMC_K28: J1.K28(HB06_P_CC)
SNN_FMC_K29: J1.K29(HB06_N_CC)
SNN_FMC_K31: J1.K31(HB10_P)
SNN_FMC_K32: J1.K32(HB10_N)
SNN_FMC_K34: J1.K34(HB14_~{P})
SNN_FMC_K35: J1.K35(HB14_N)
SNN_FMC_K37: J1.K37(HB17_P_CC)
SNN_FMC_K38: J1.K38(HB17_N_CC)
SNN_FMC_RES0: J1.B40(RES0)
VIO_B_M2C_J39: J1.J39(VIO_B_M2C-1) TP20.1(TP)
VIO_B_M2C_K40: J1.K40(VIO_B_M2C-2) TP19.1(TP)
VREF_B_M2C_H1: J1.H1(VREF_A_M2C) TP8.1(TP)
VREF_B_M2C_K1: J1.K1(VREF_B_M2C) TP18.1(TP)
N20860287: C216.1 C217.1 C218.1 C219.1 C220.1 C221.1 C223.1 LB22.1 U3.F8(VCCAUX) U3.G7(VCCAUX) U3.K8(VCCAUXH4) U3.K10(VCCAUXH3) U3.M6(VCCAUXH5)
N20861643: C222.1 C224.1 LB23.1 U3.F7(VCCAUX)

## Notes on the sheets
sheet 9
- CrossLink-NX Config FLASH
- Bank-0
- Bank-1
- 125MHz
- Bank-3
sheet 10
- Bank-4
- Bank-5
- Bank-6
- Bank-7
sheet 11
- CrossLink-NX  NC Pin
- CrossLink-NX Core Power
- CrossLink-NX Ground
sheet 12
- VDD_2V8_LDO is not connected
- VDD_2V8_LDO is not connected
sheet 15
- I2C 7-bit address = 0x50
- I2C 7-bit address = 0x50
